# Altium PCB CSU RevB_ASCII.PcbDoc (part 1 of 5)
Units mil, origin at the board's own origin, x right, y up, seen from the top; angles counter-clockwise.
Board outline 5905.51 x 4330.71 mil, 8 copper layers (Top Layer, InternalPlane1, MidLayer1, InternalPlane2, MidLayer2, InternalPlane3, MidLayer3, Bottom Layer); 265 components, 387 nets, 1910 pads, 1151 vias.
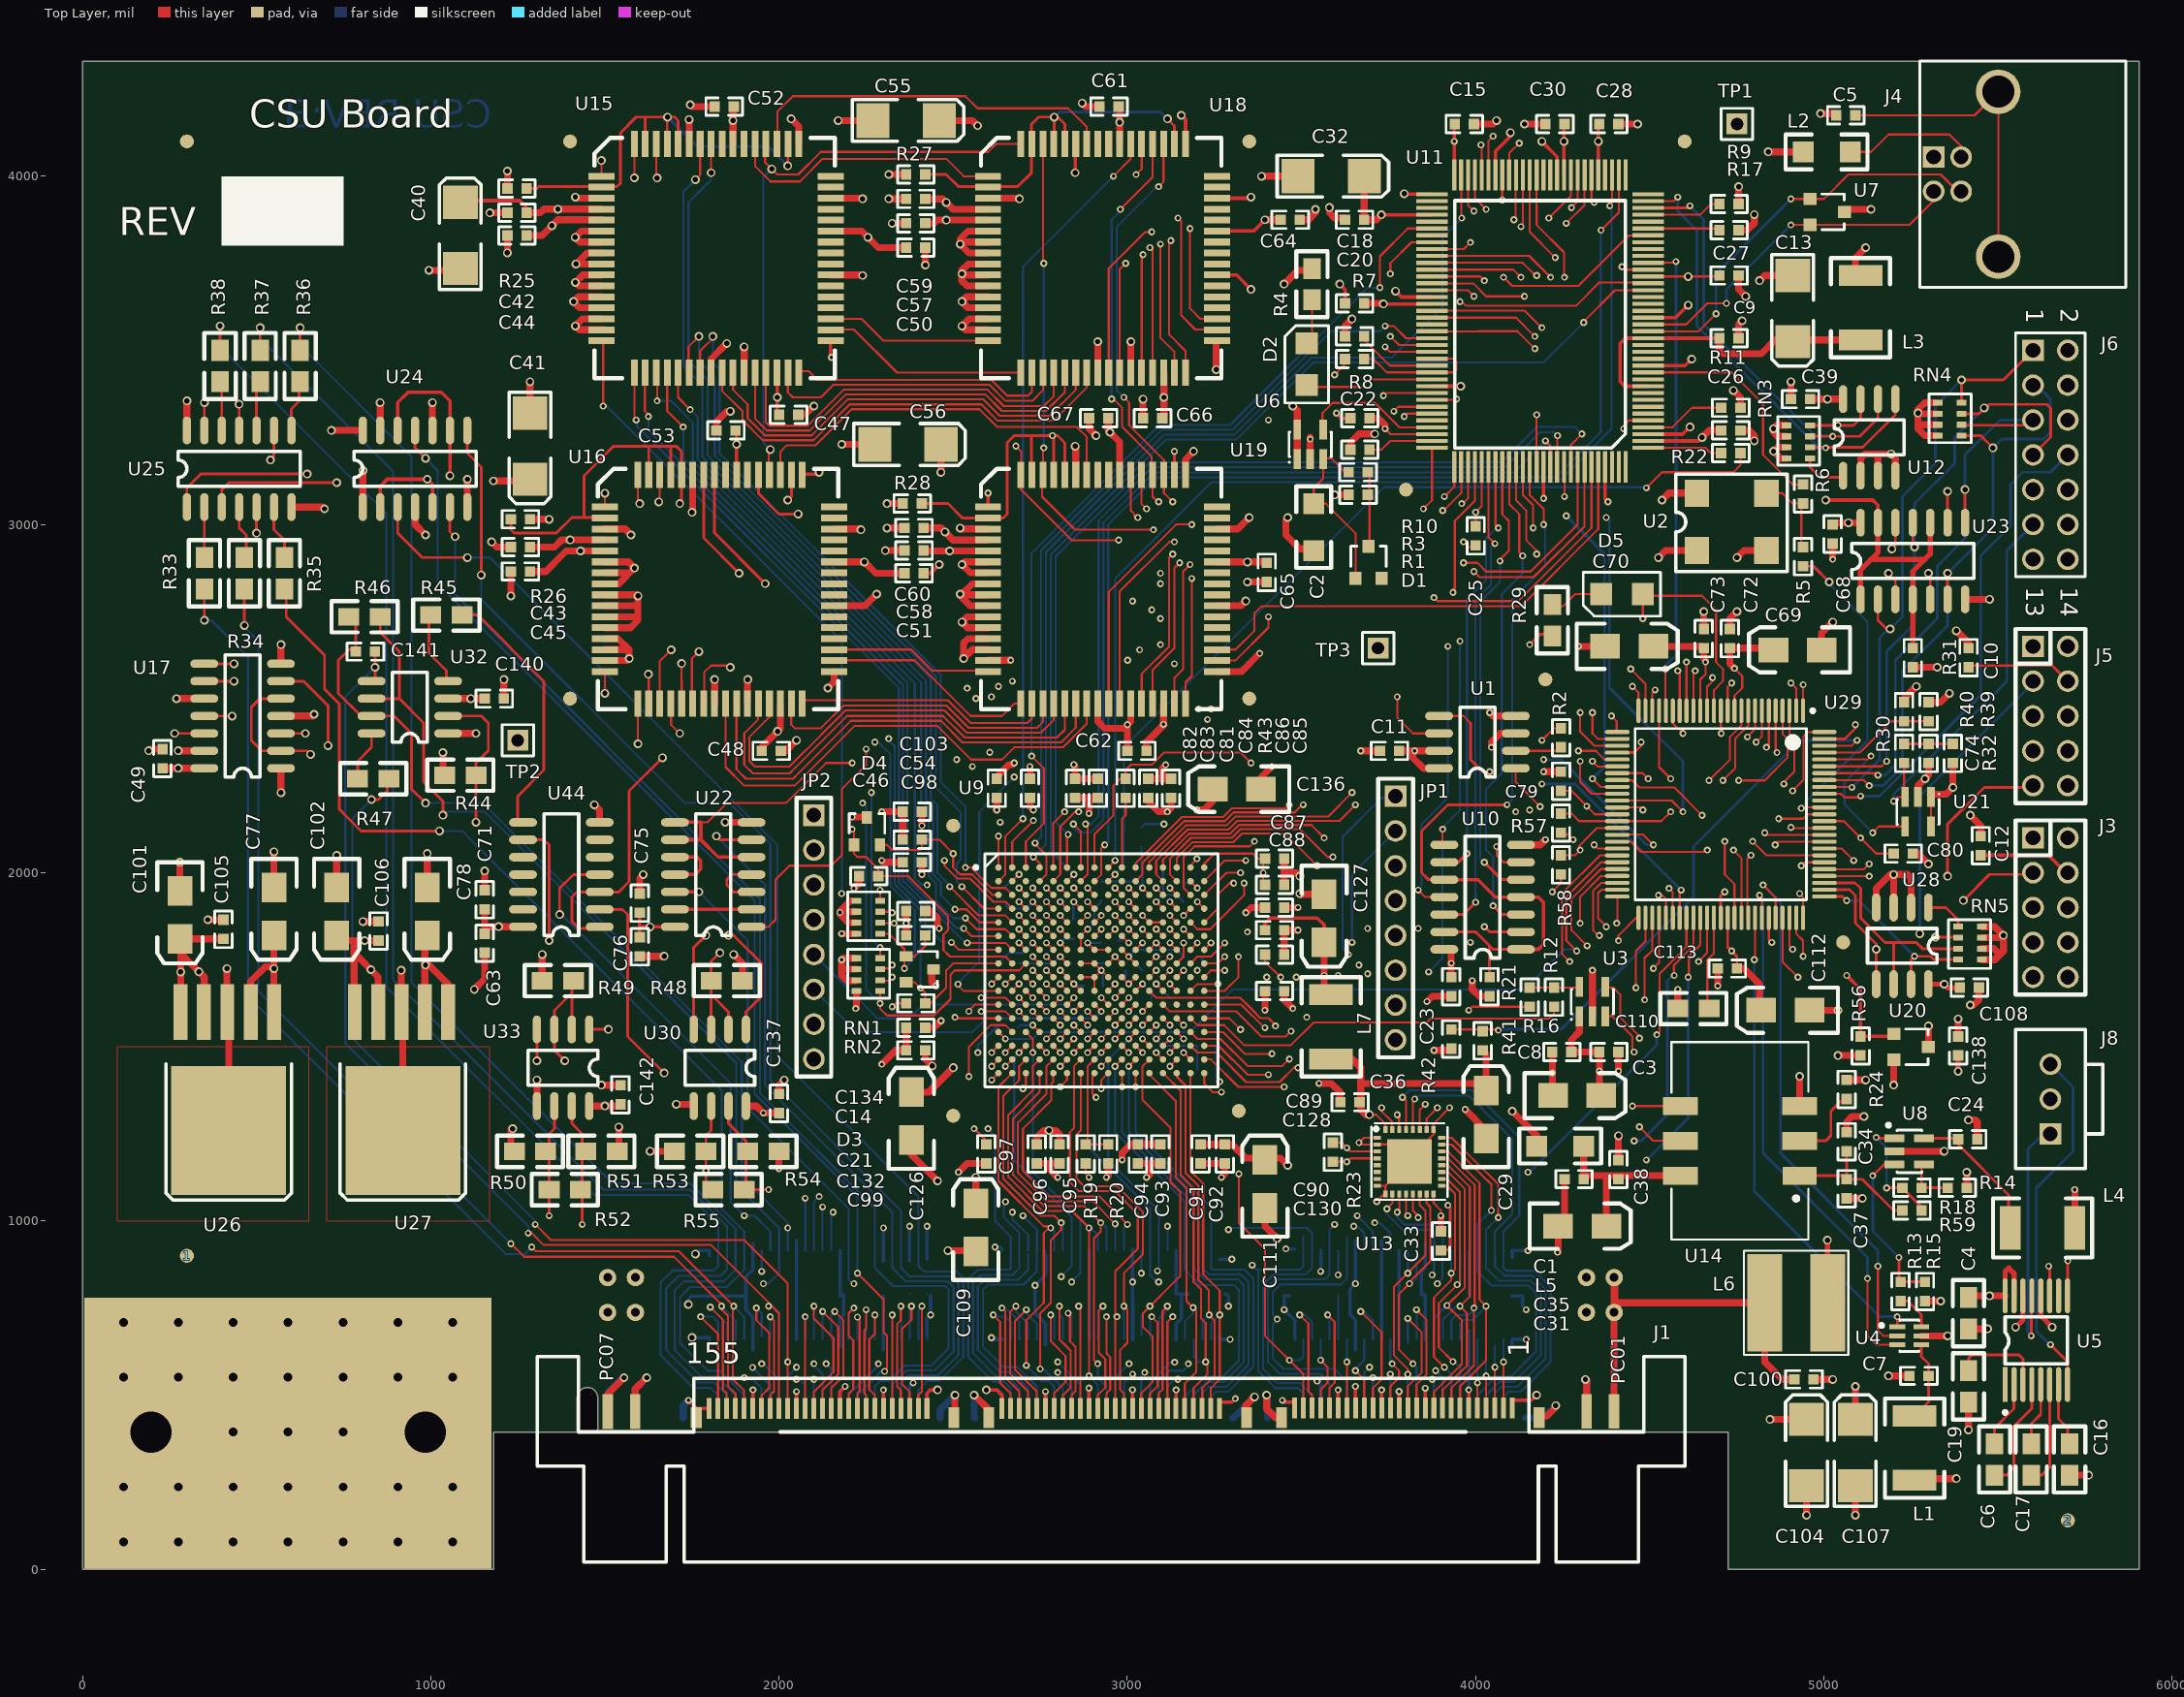
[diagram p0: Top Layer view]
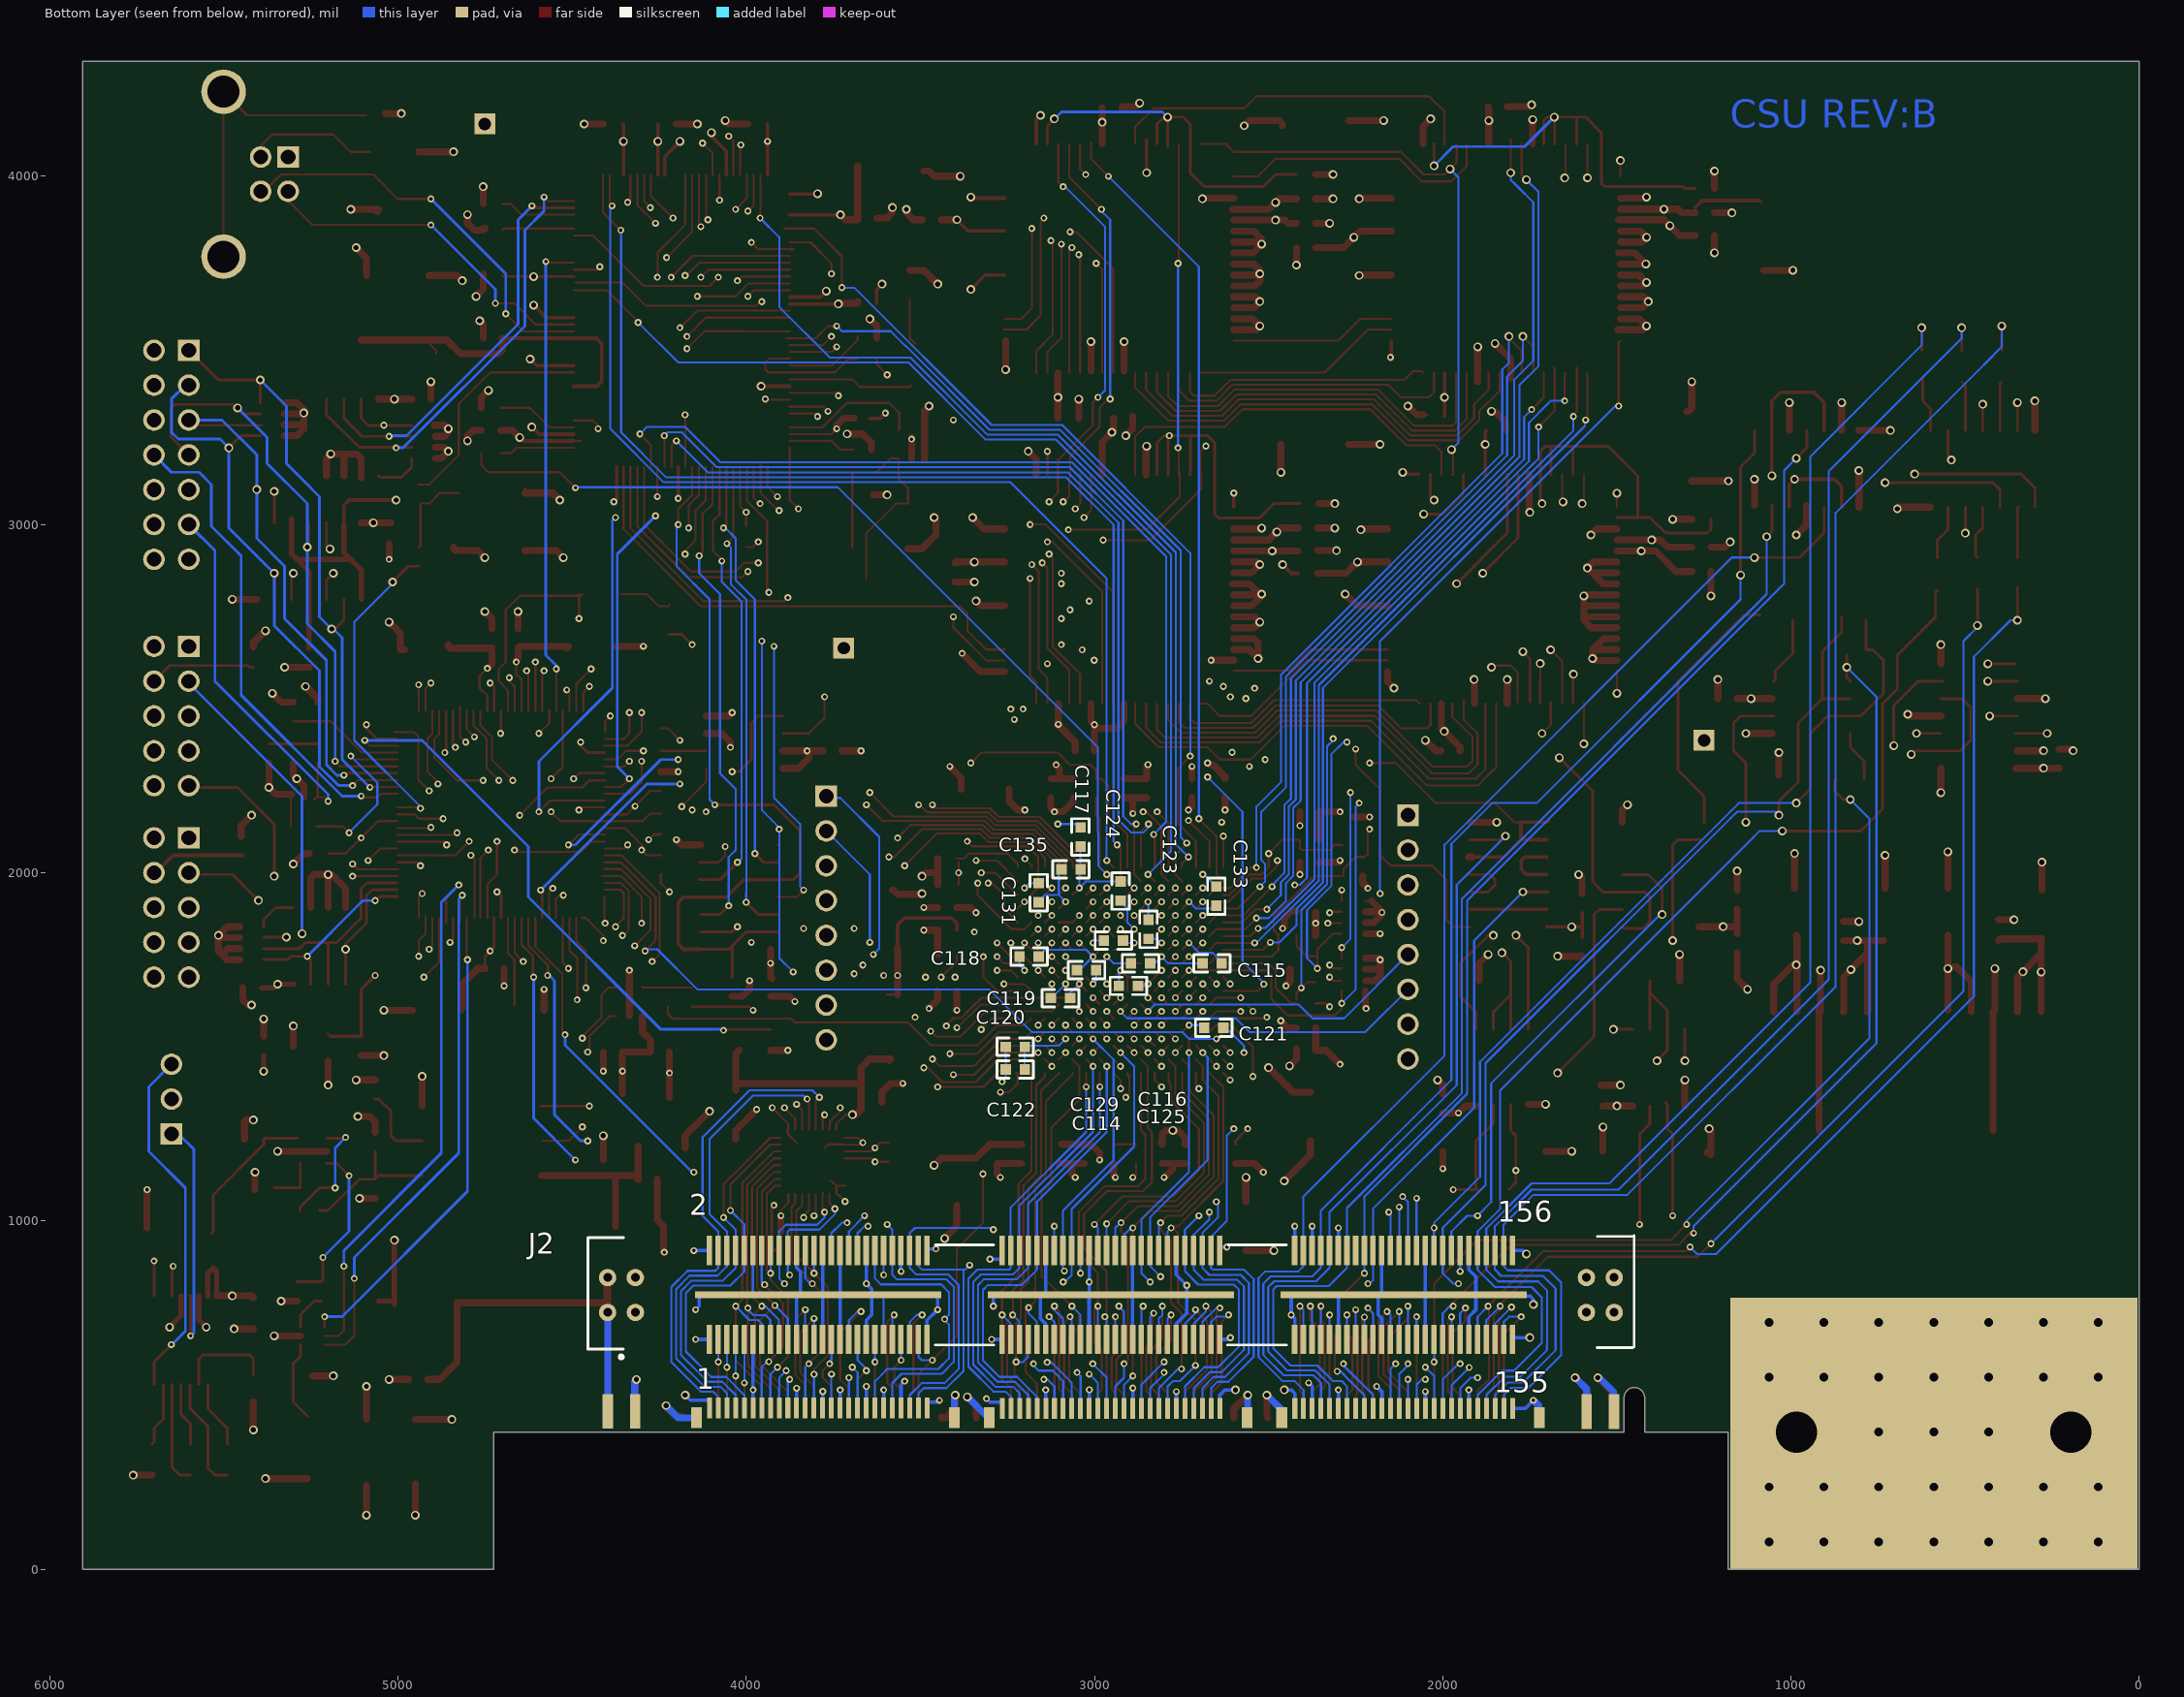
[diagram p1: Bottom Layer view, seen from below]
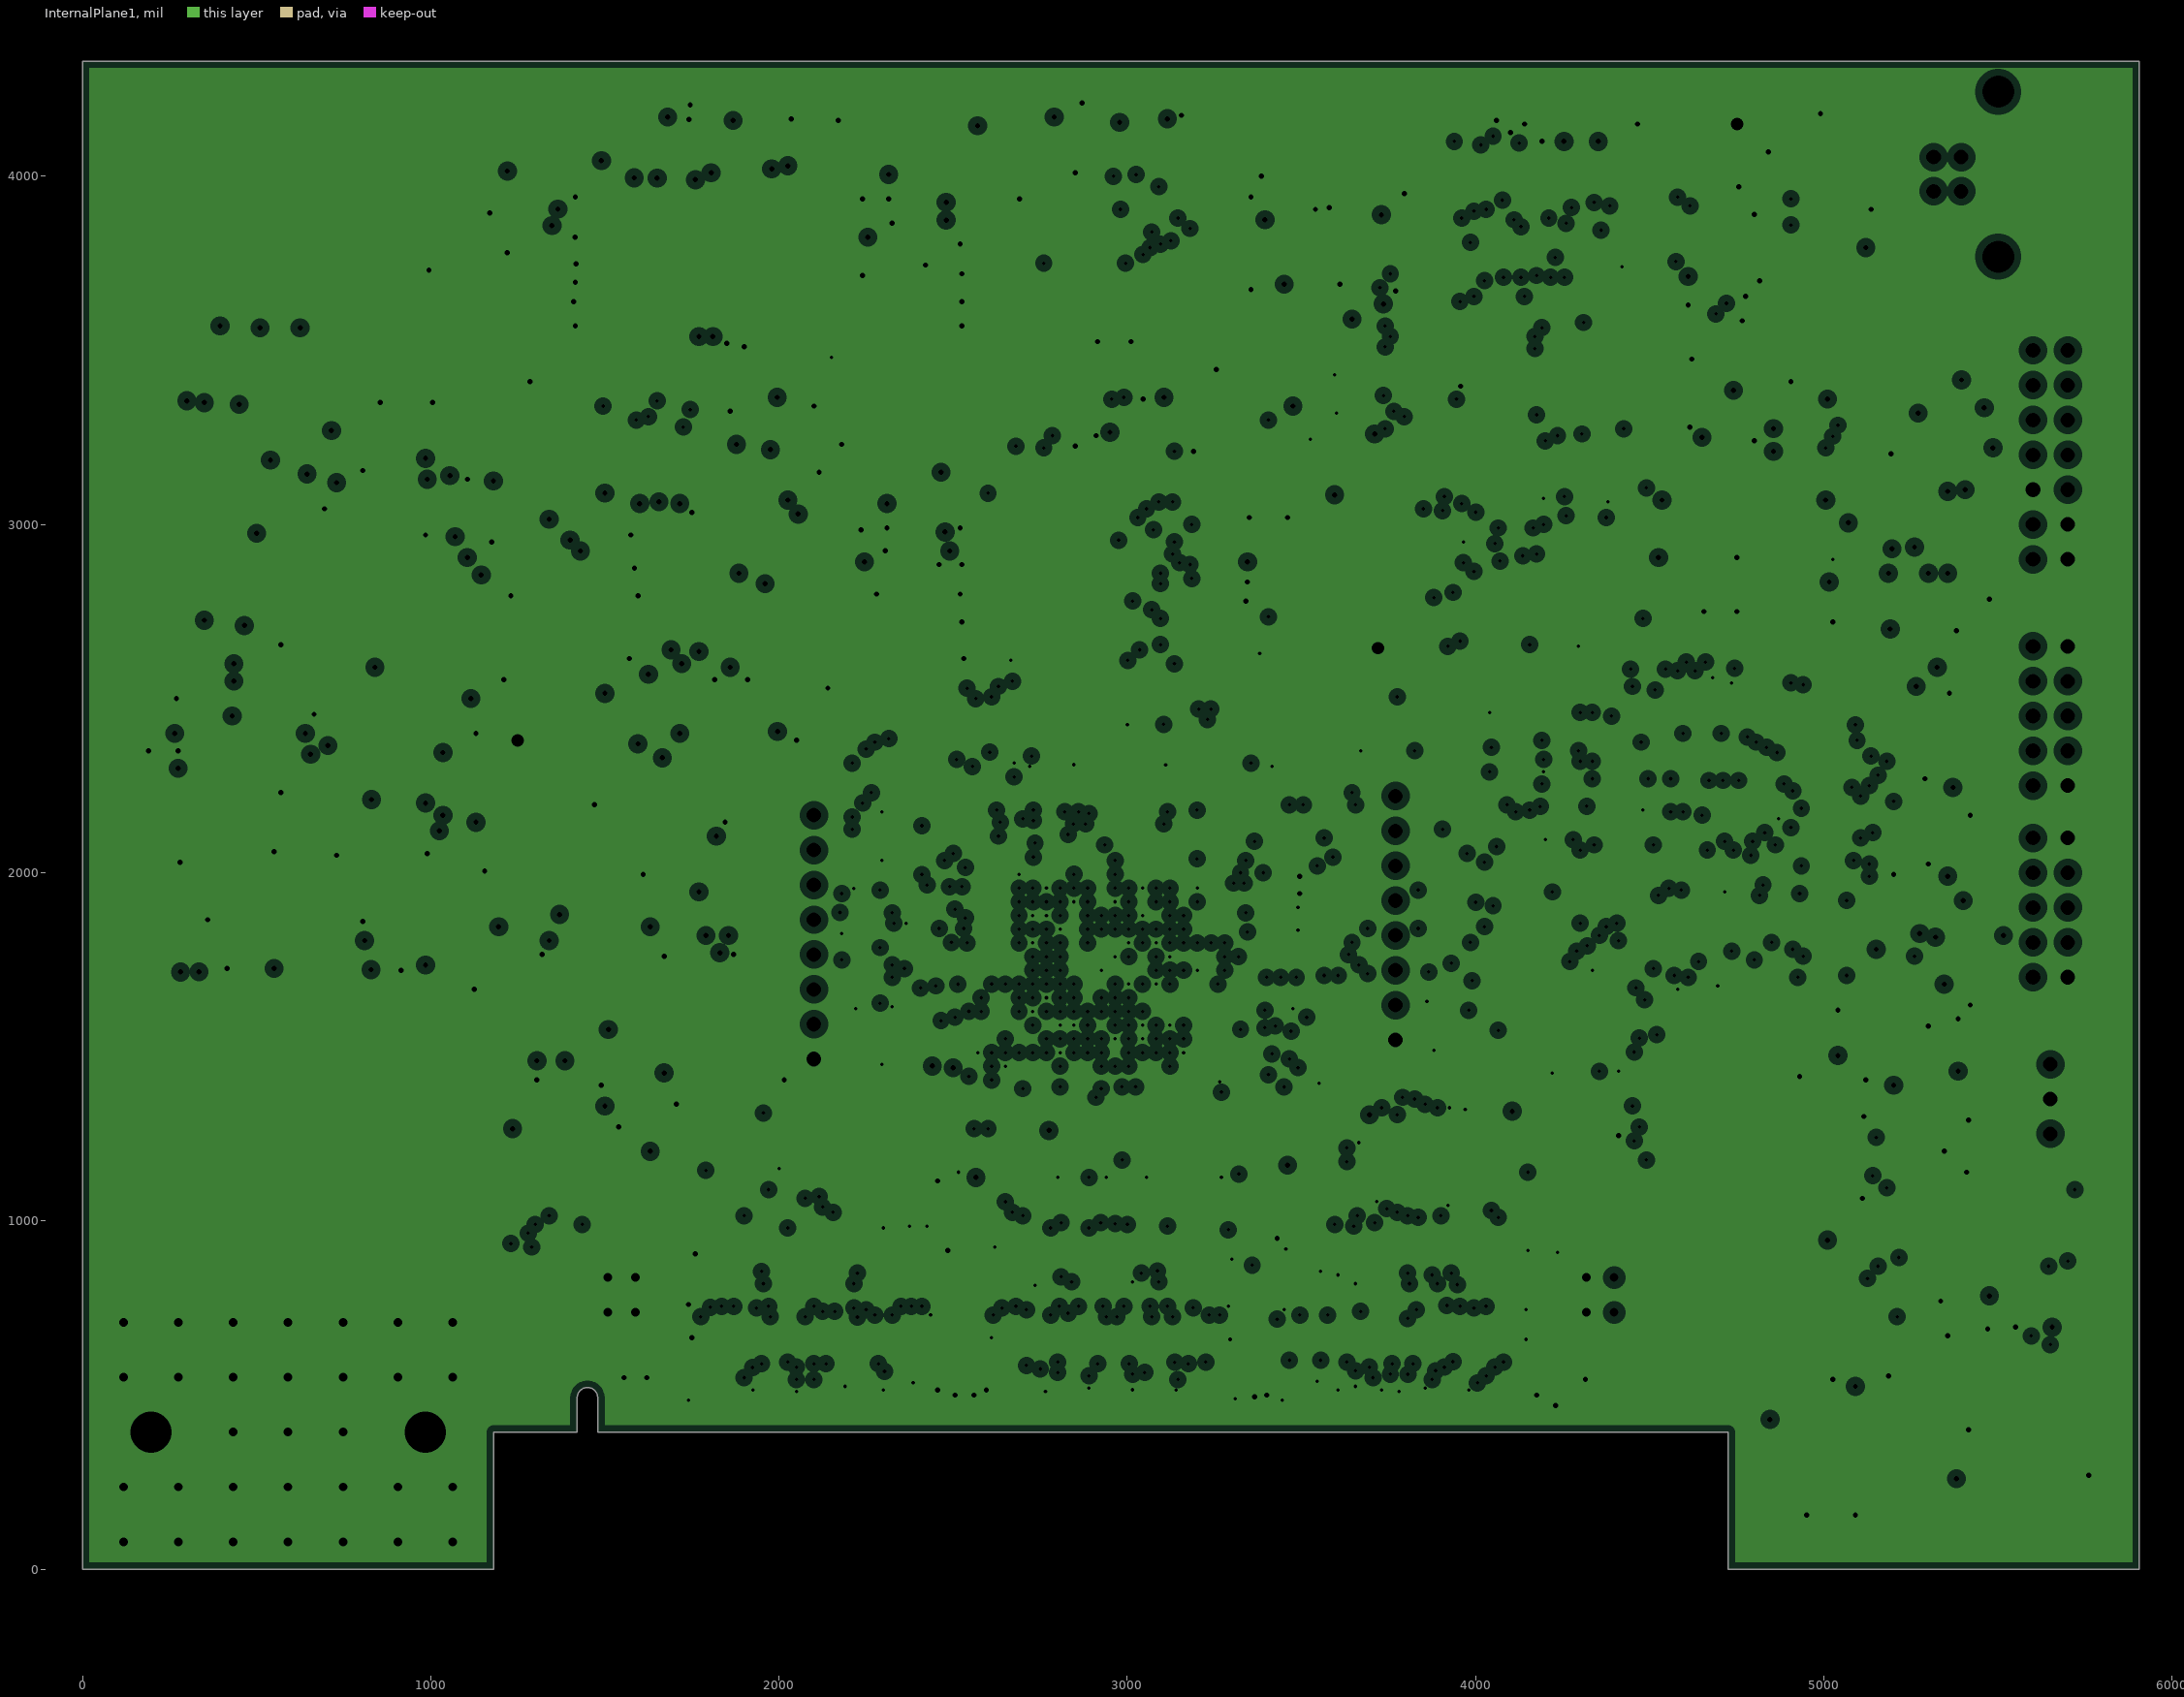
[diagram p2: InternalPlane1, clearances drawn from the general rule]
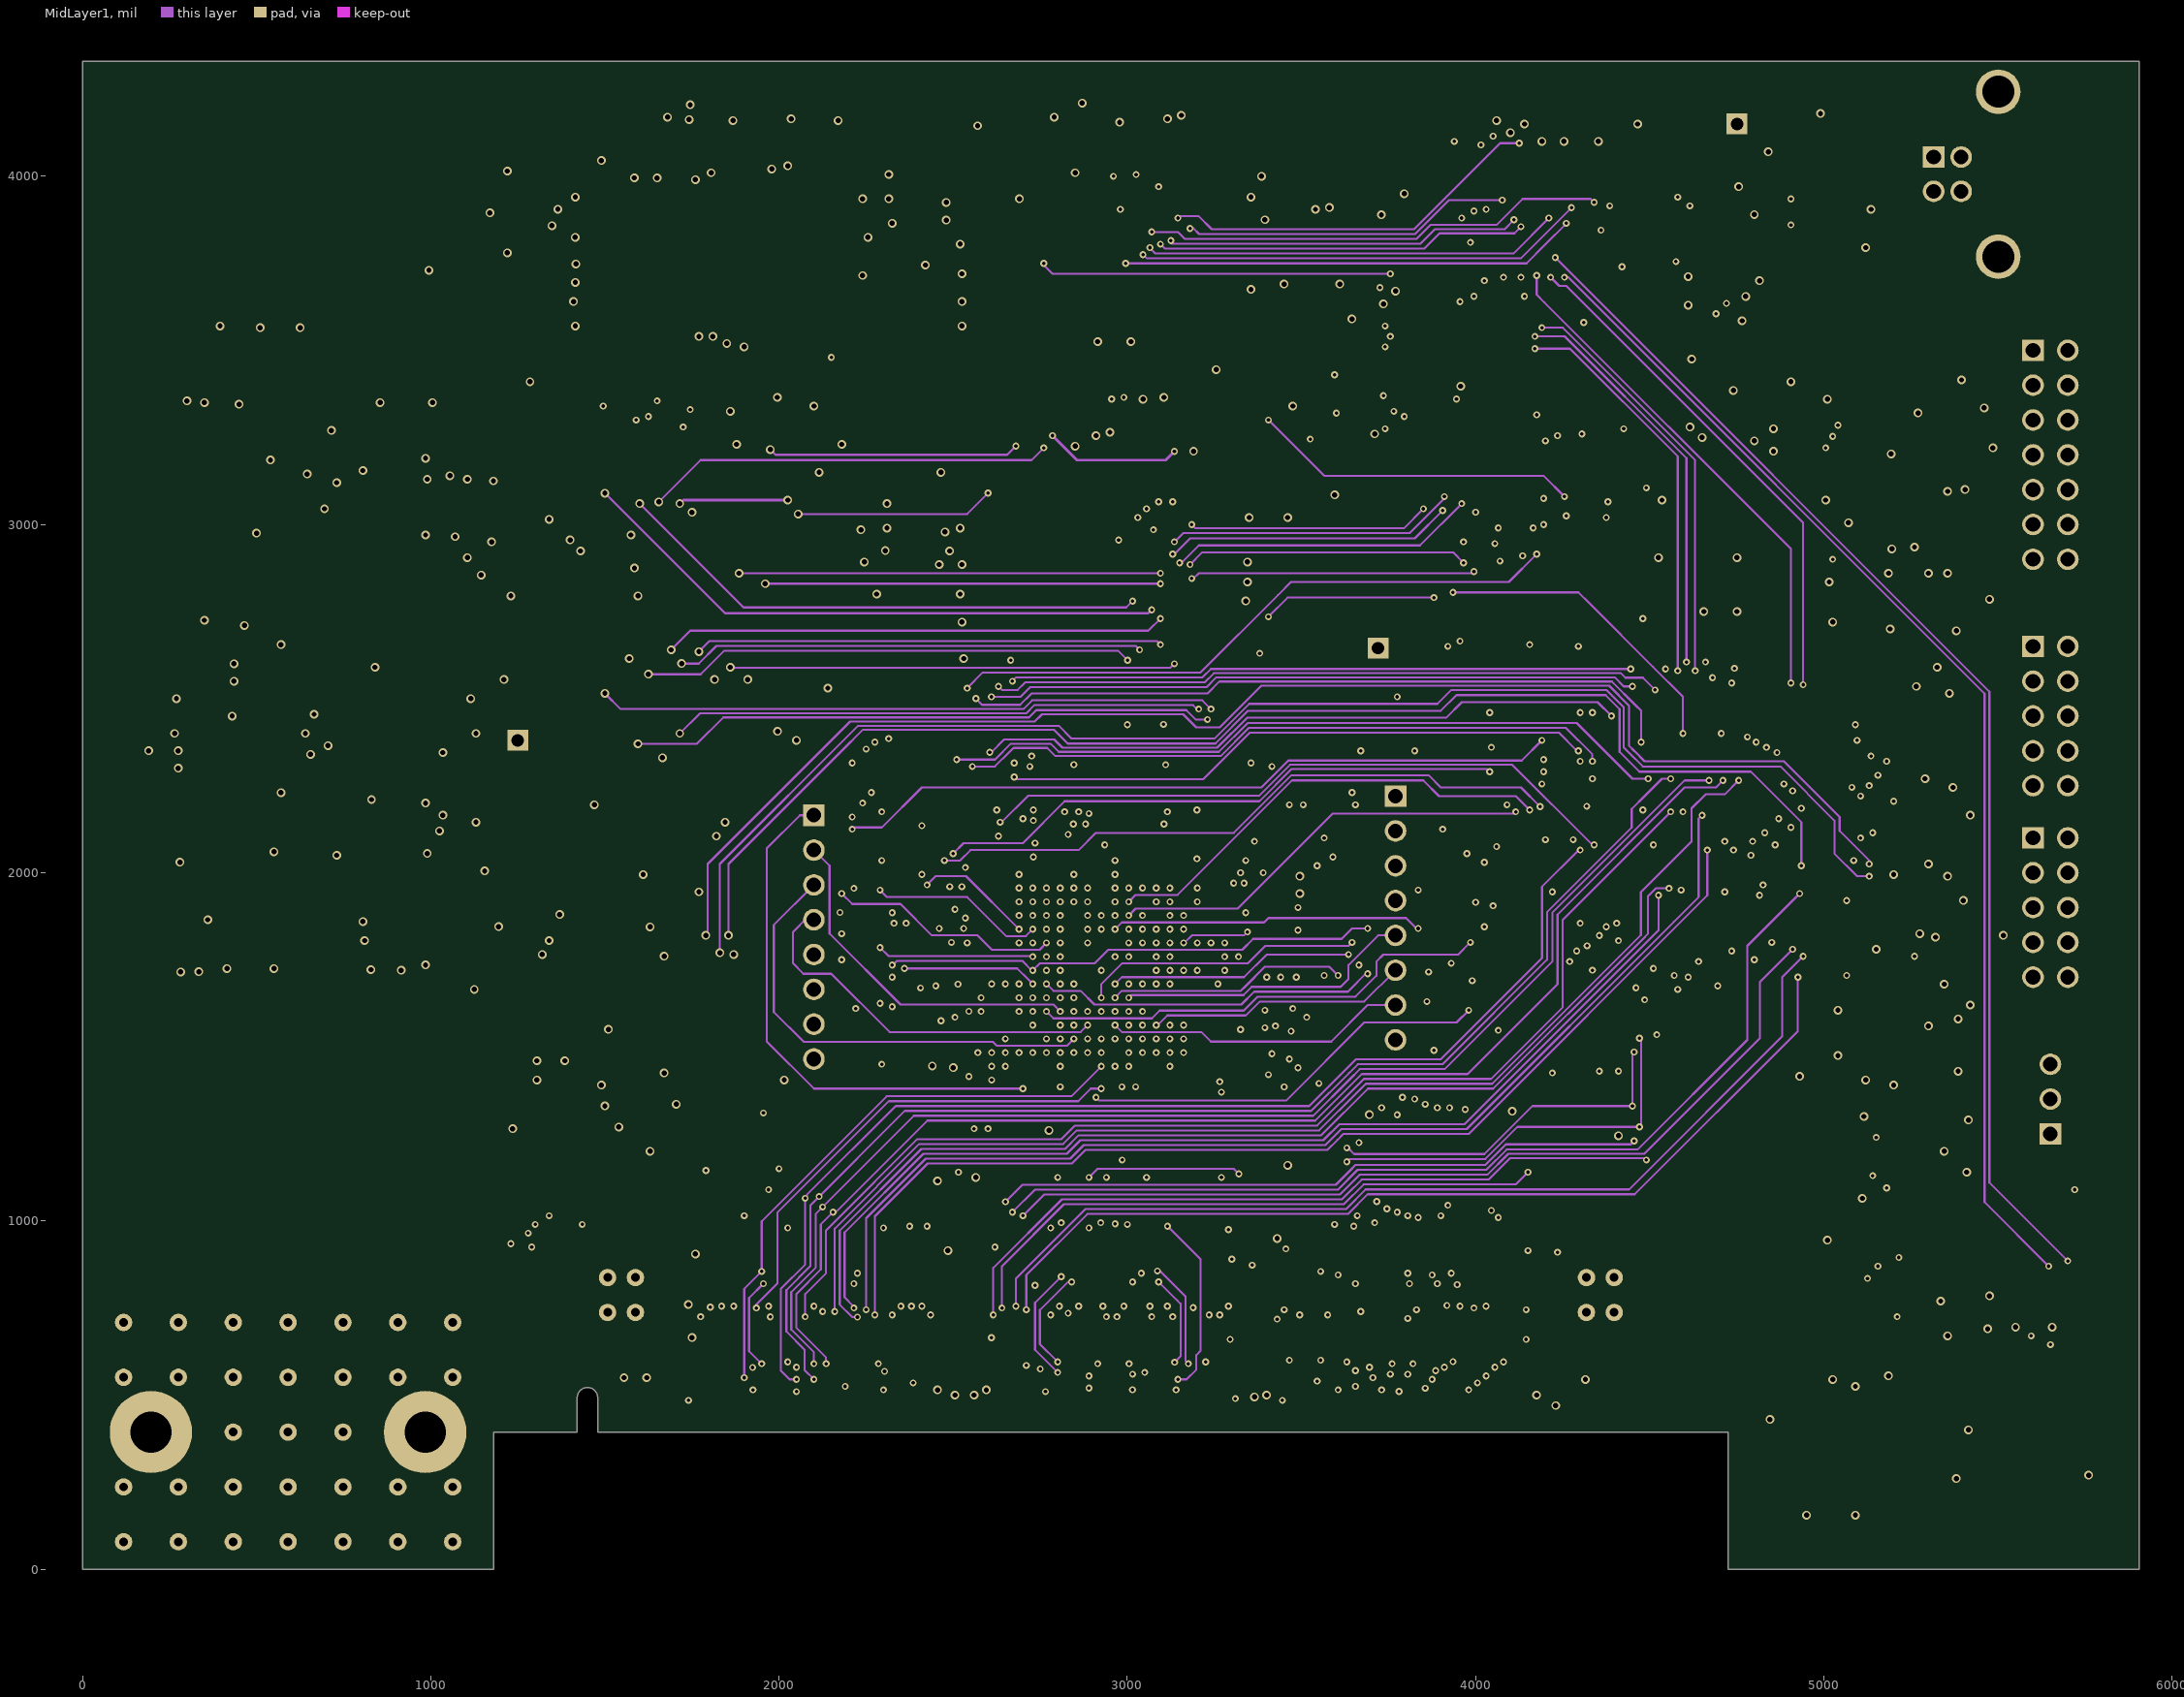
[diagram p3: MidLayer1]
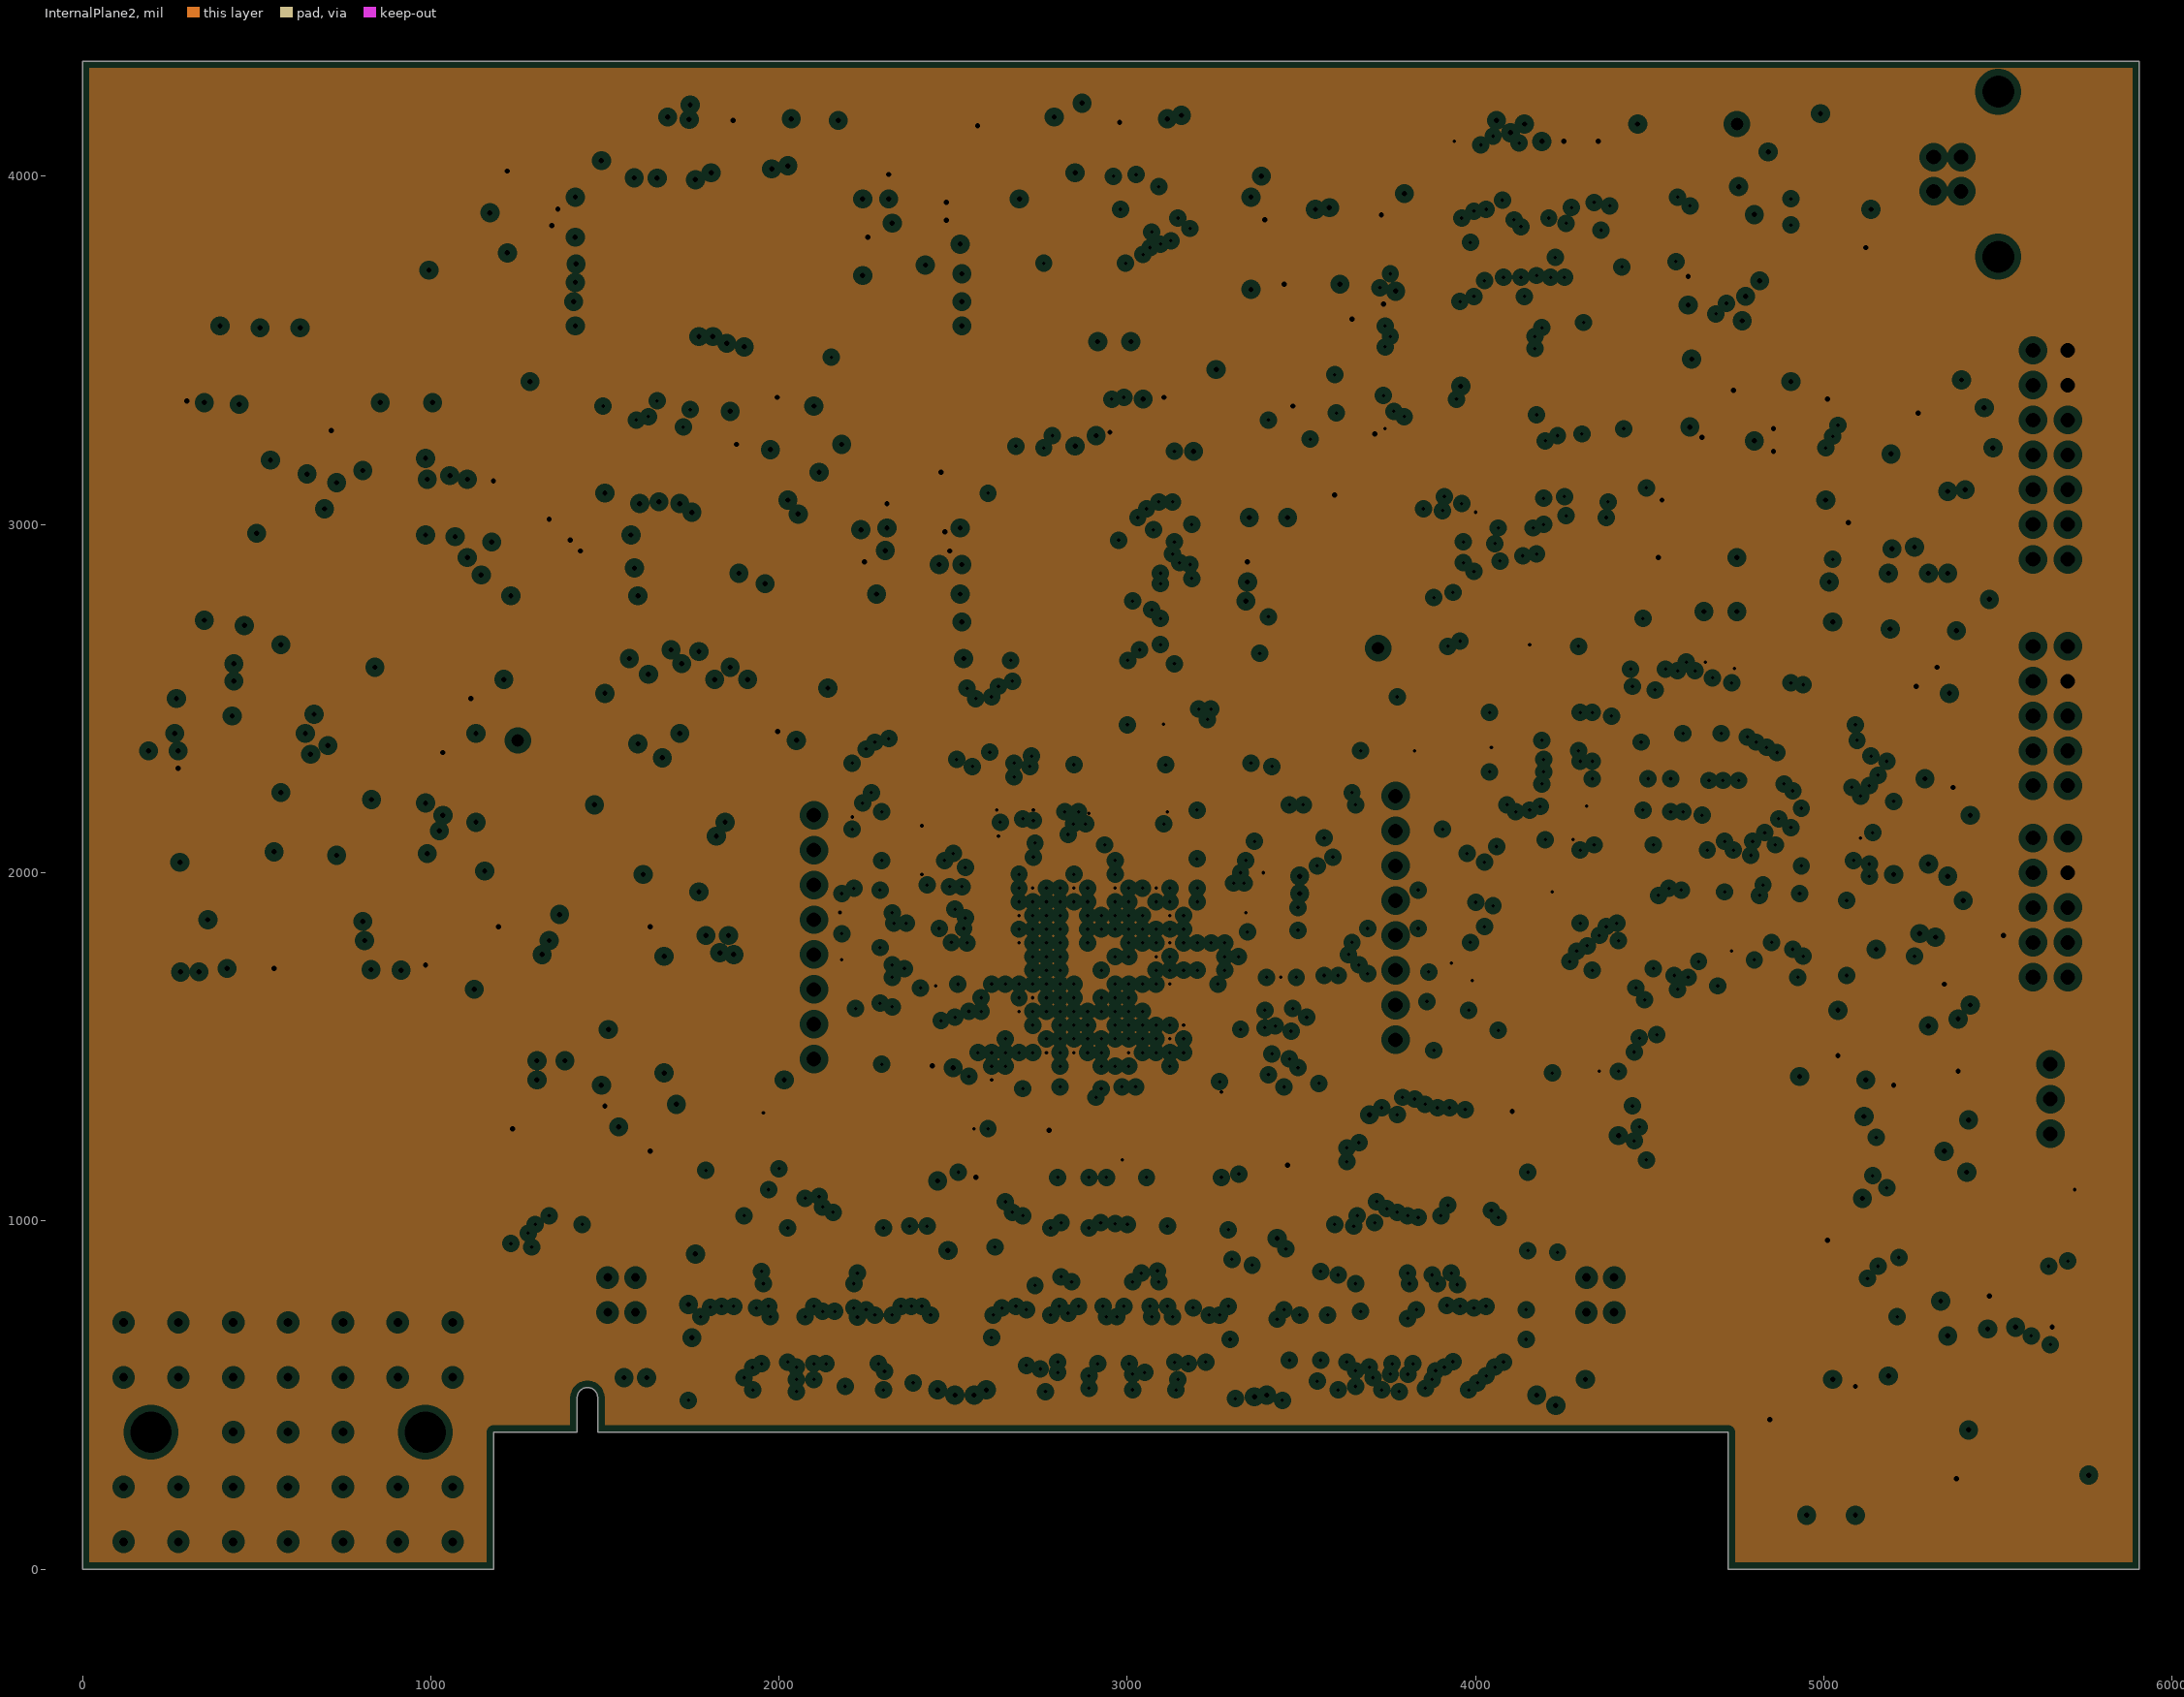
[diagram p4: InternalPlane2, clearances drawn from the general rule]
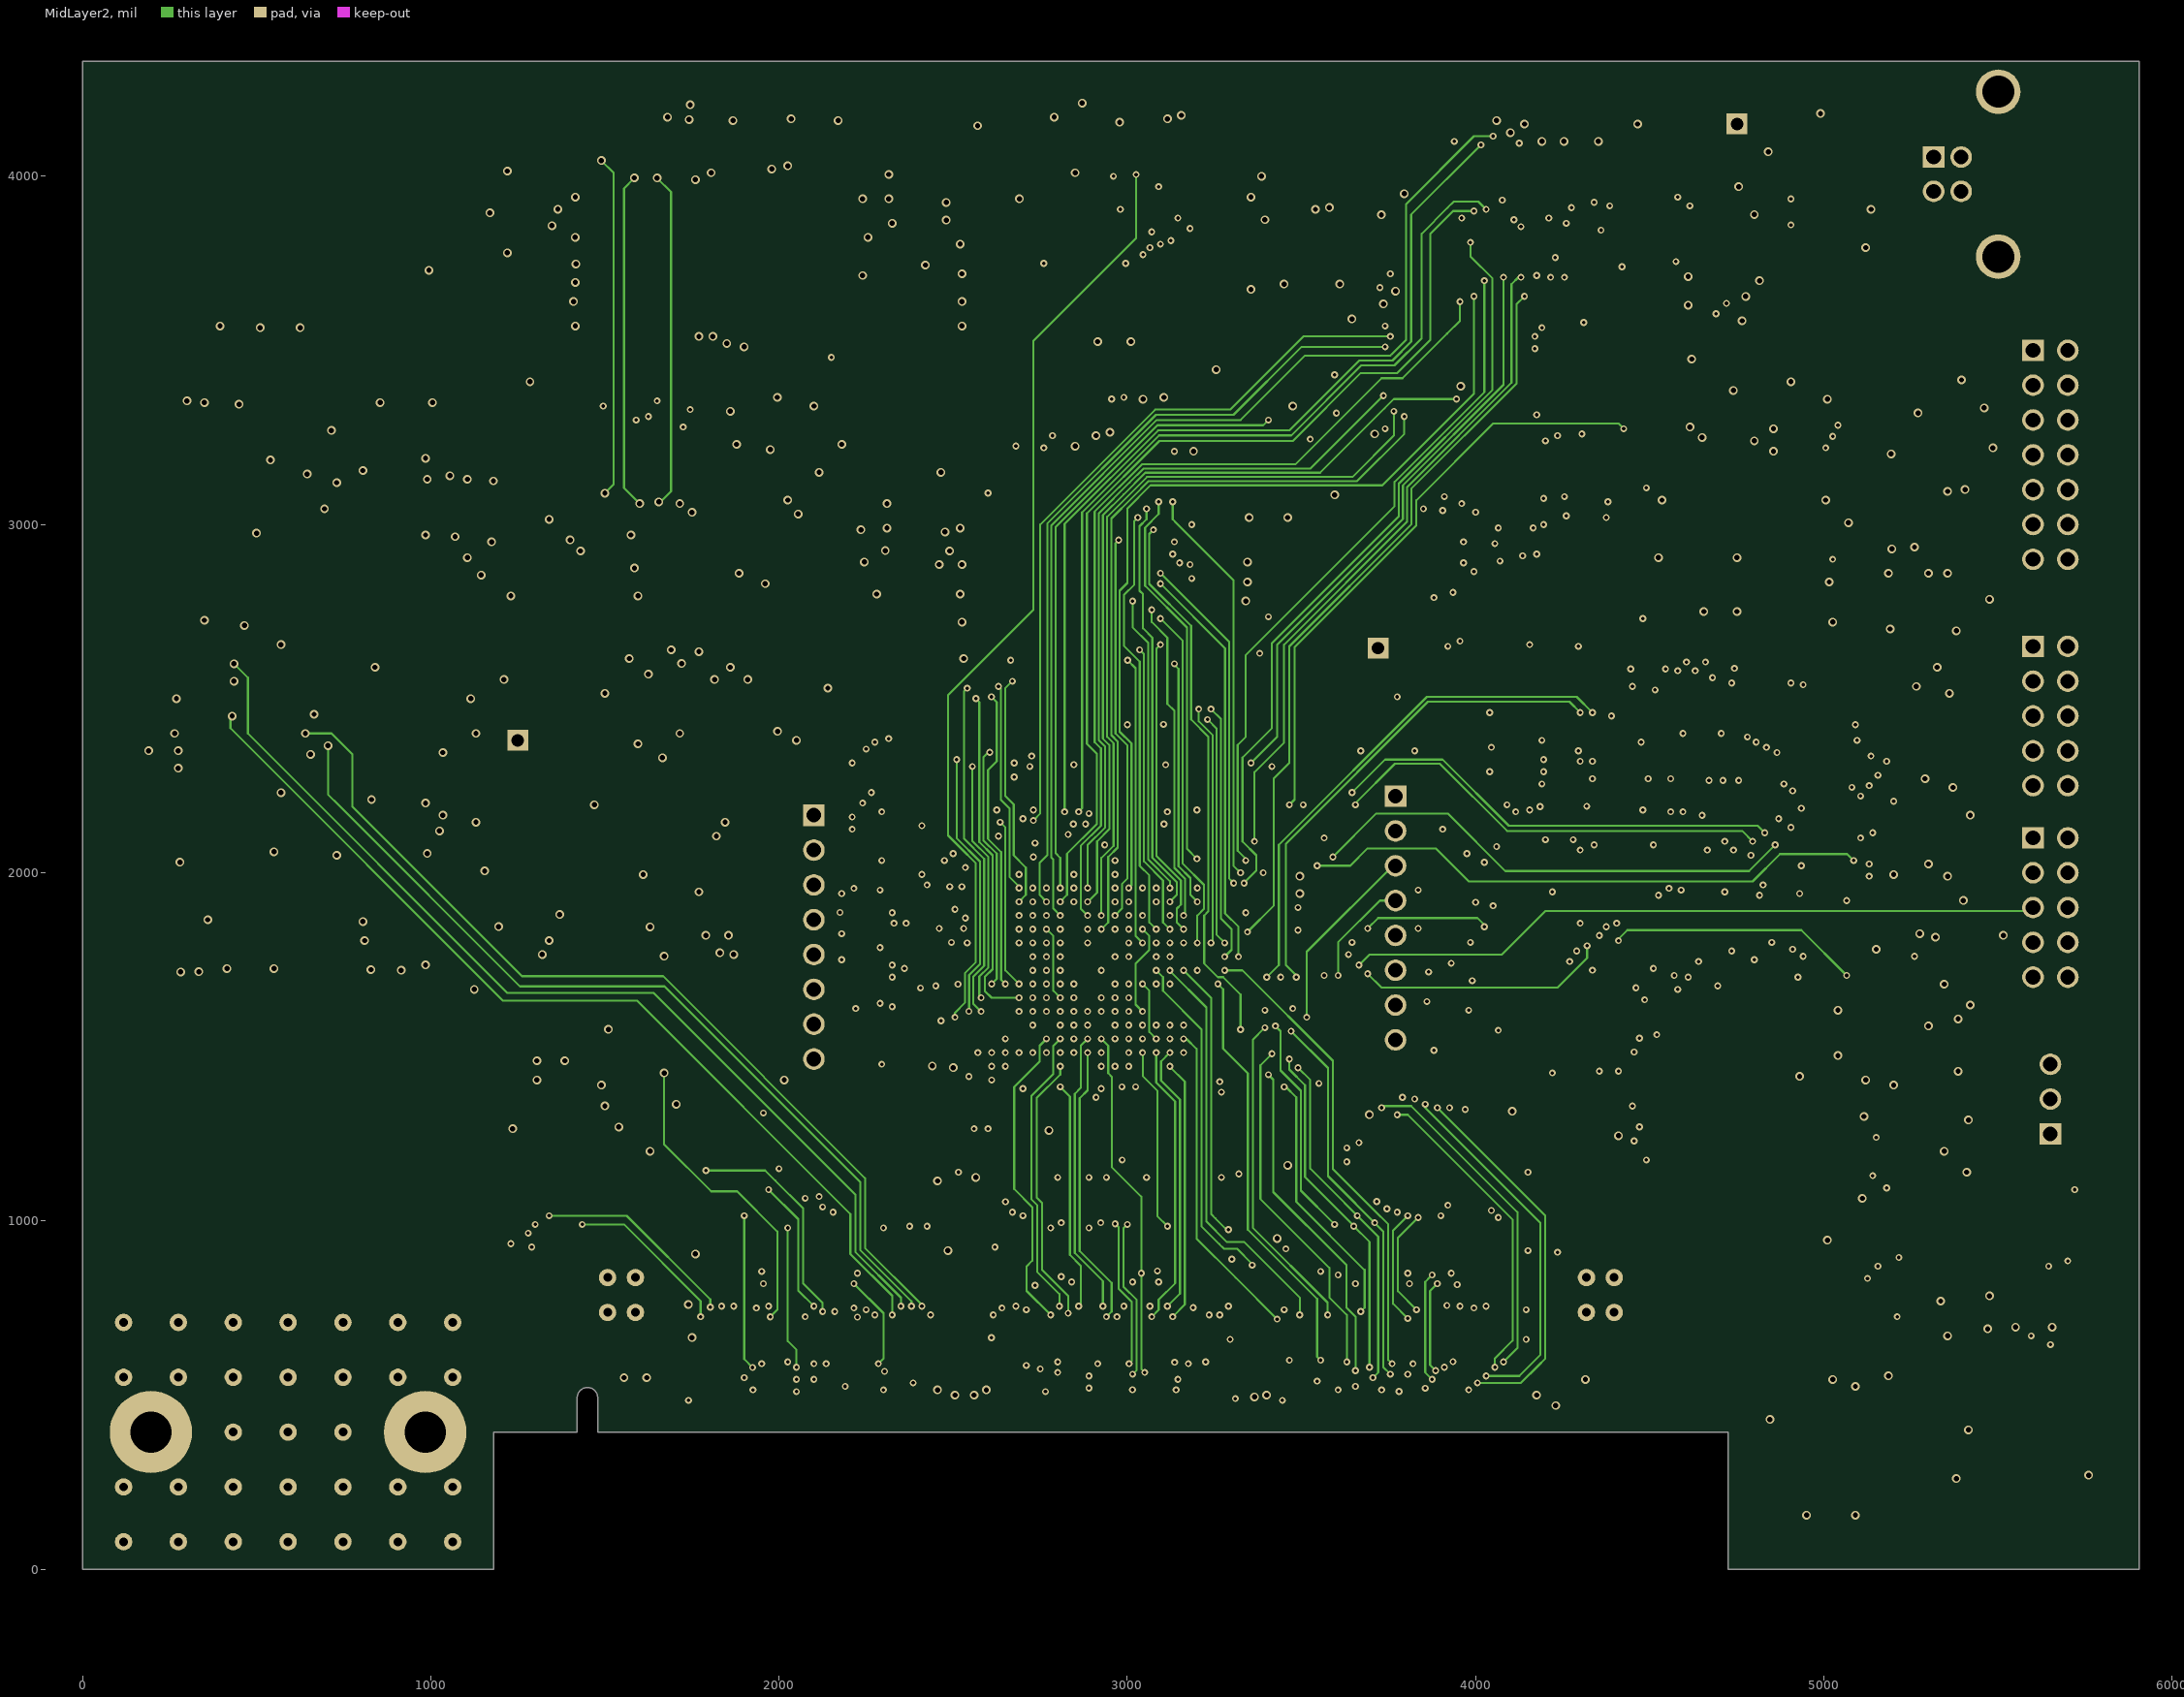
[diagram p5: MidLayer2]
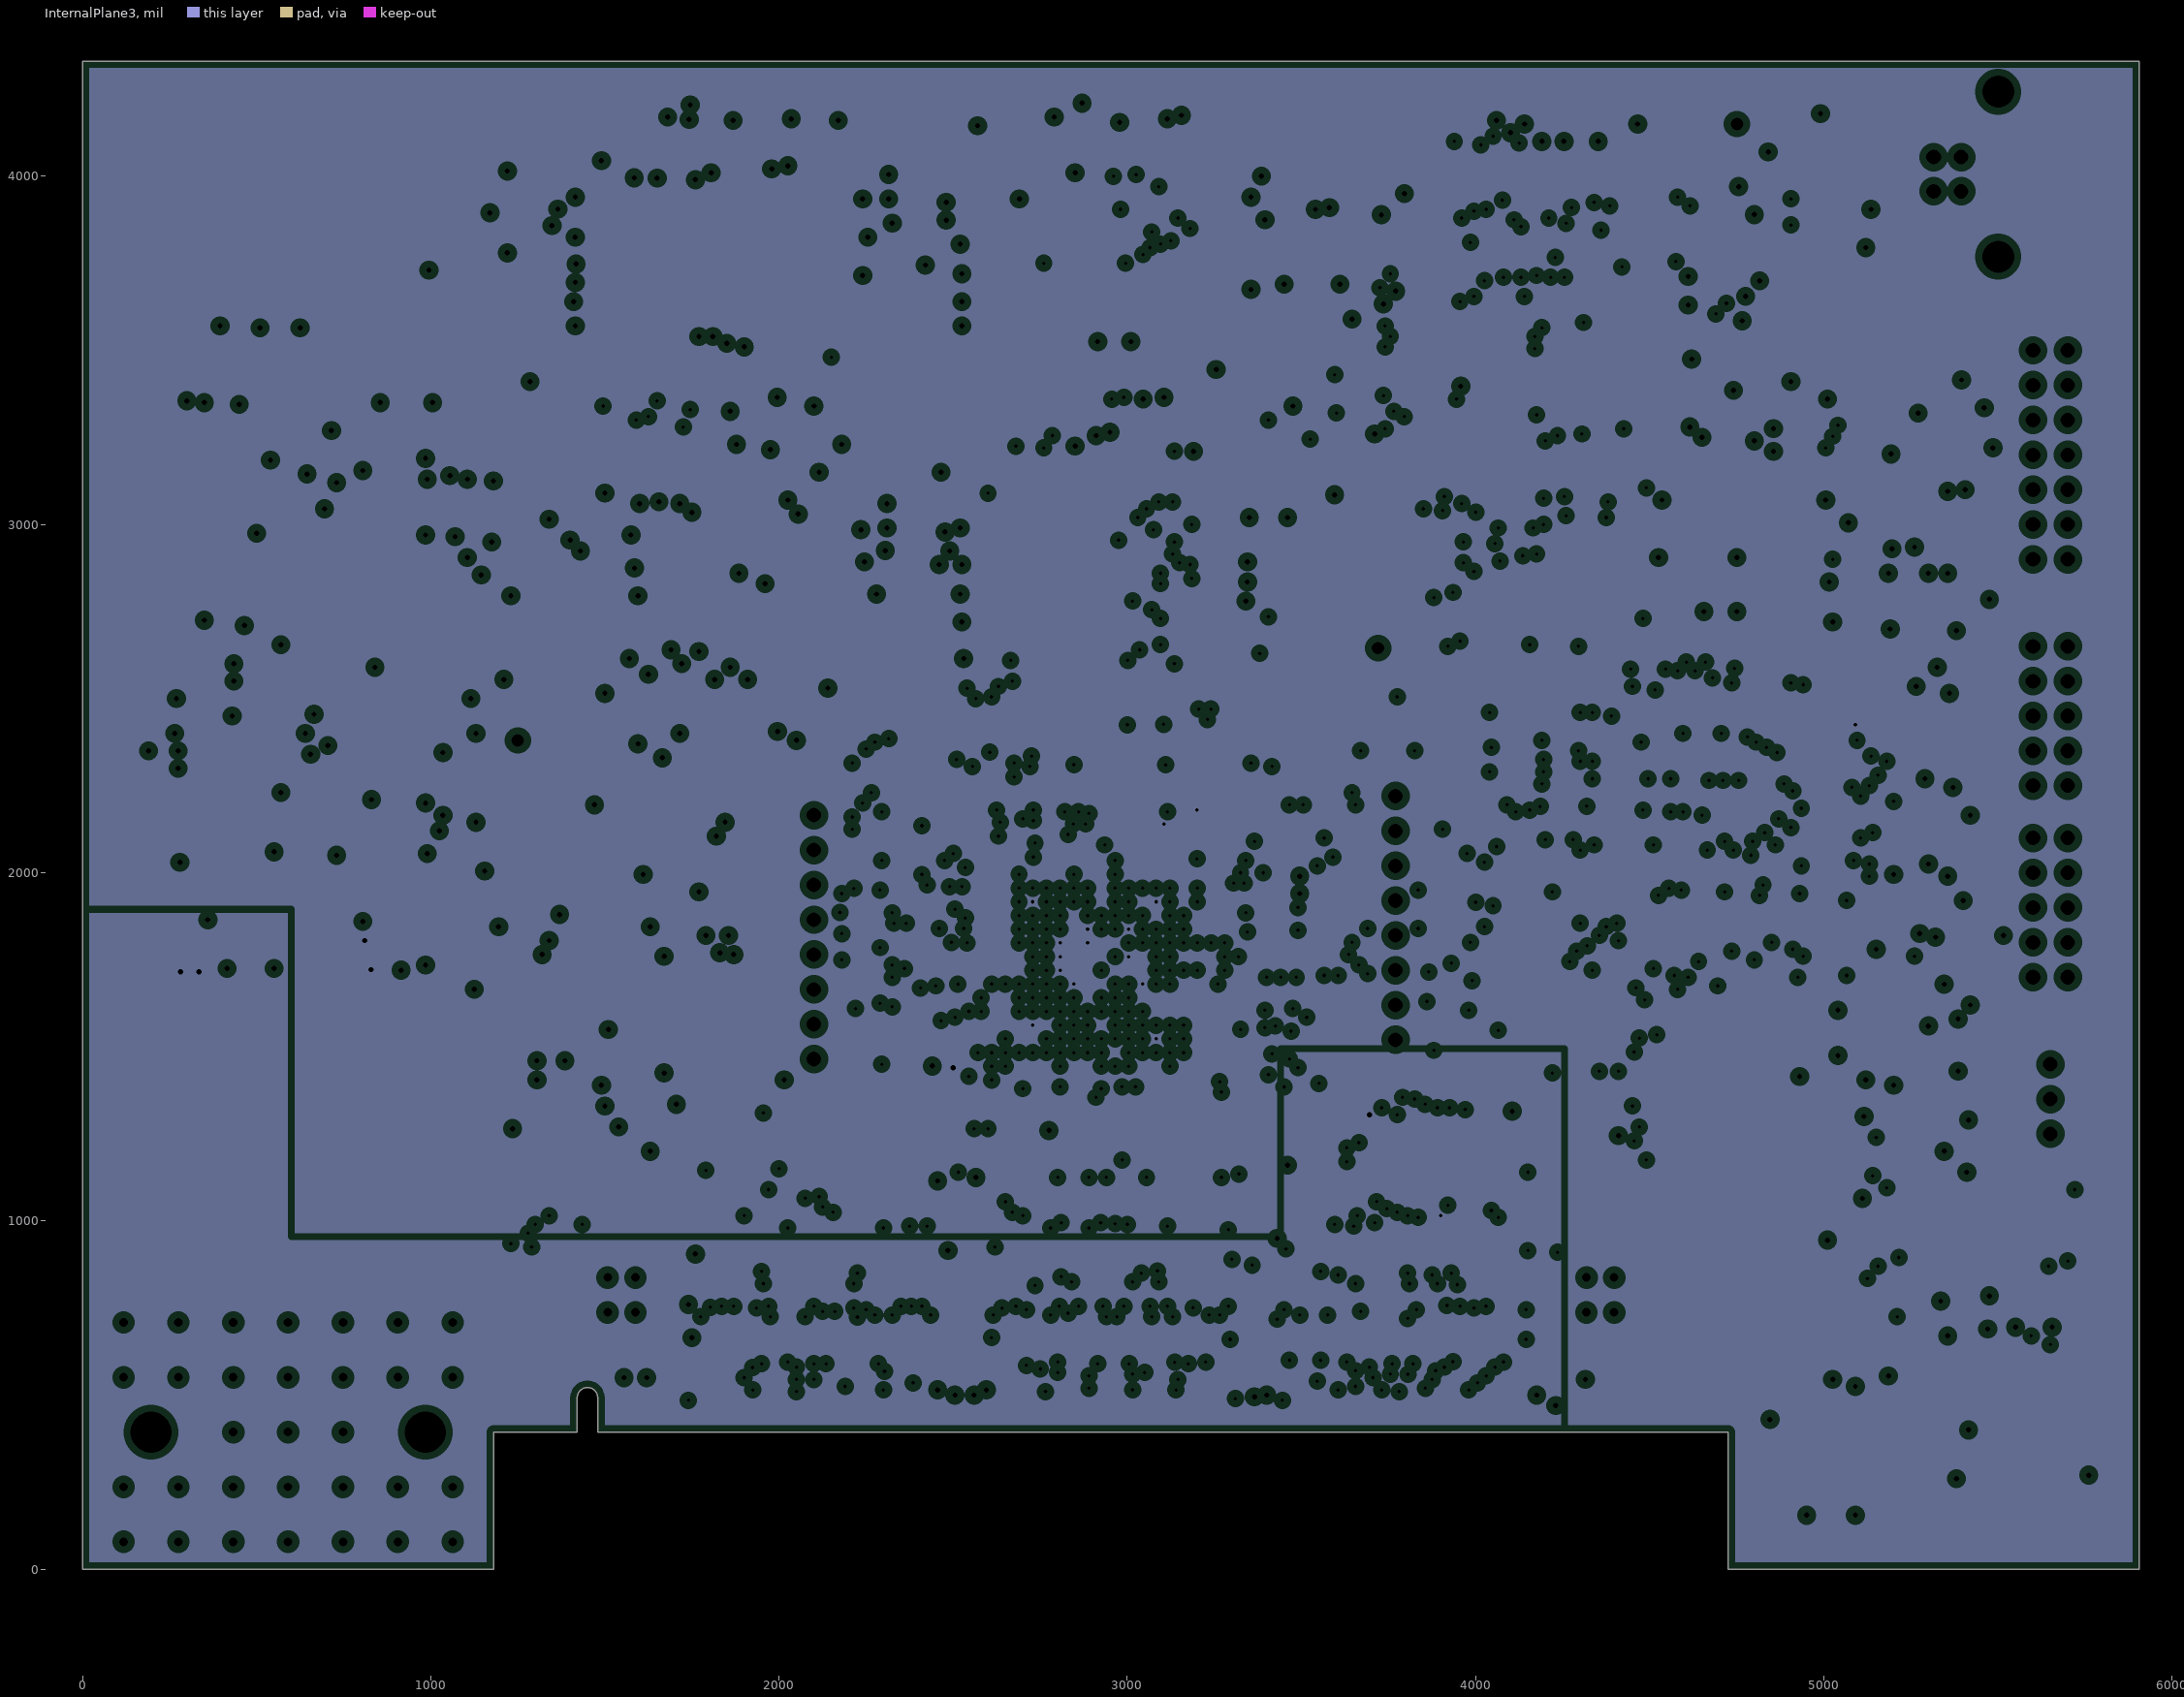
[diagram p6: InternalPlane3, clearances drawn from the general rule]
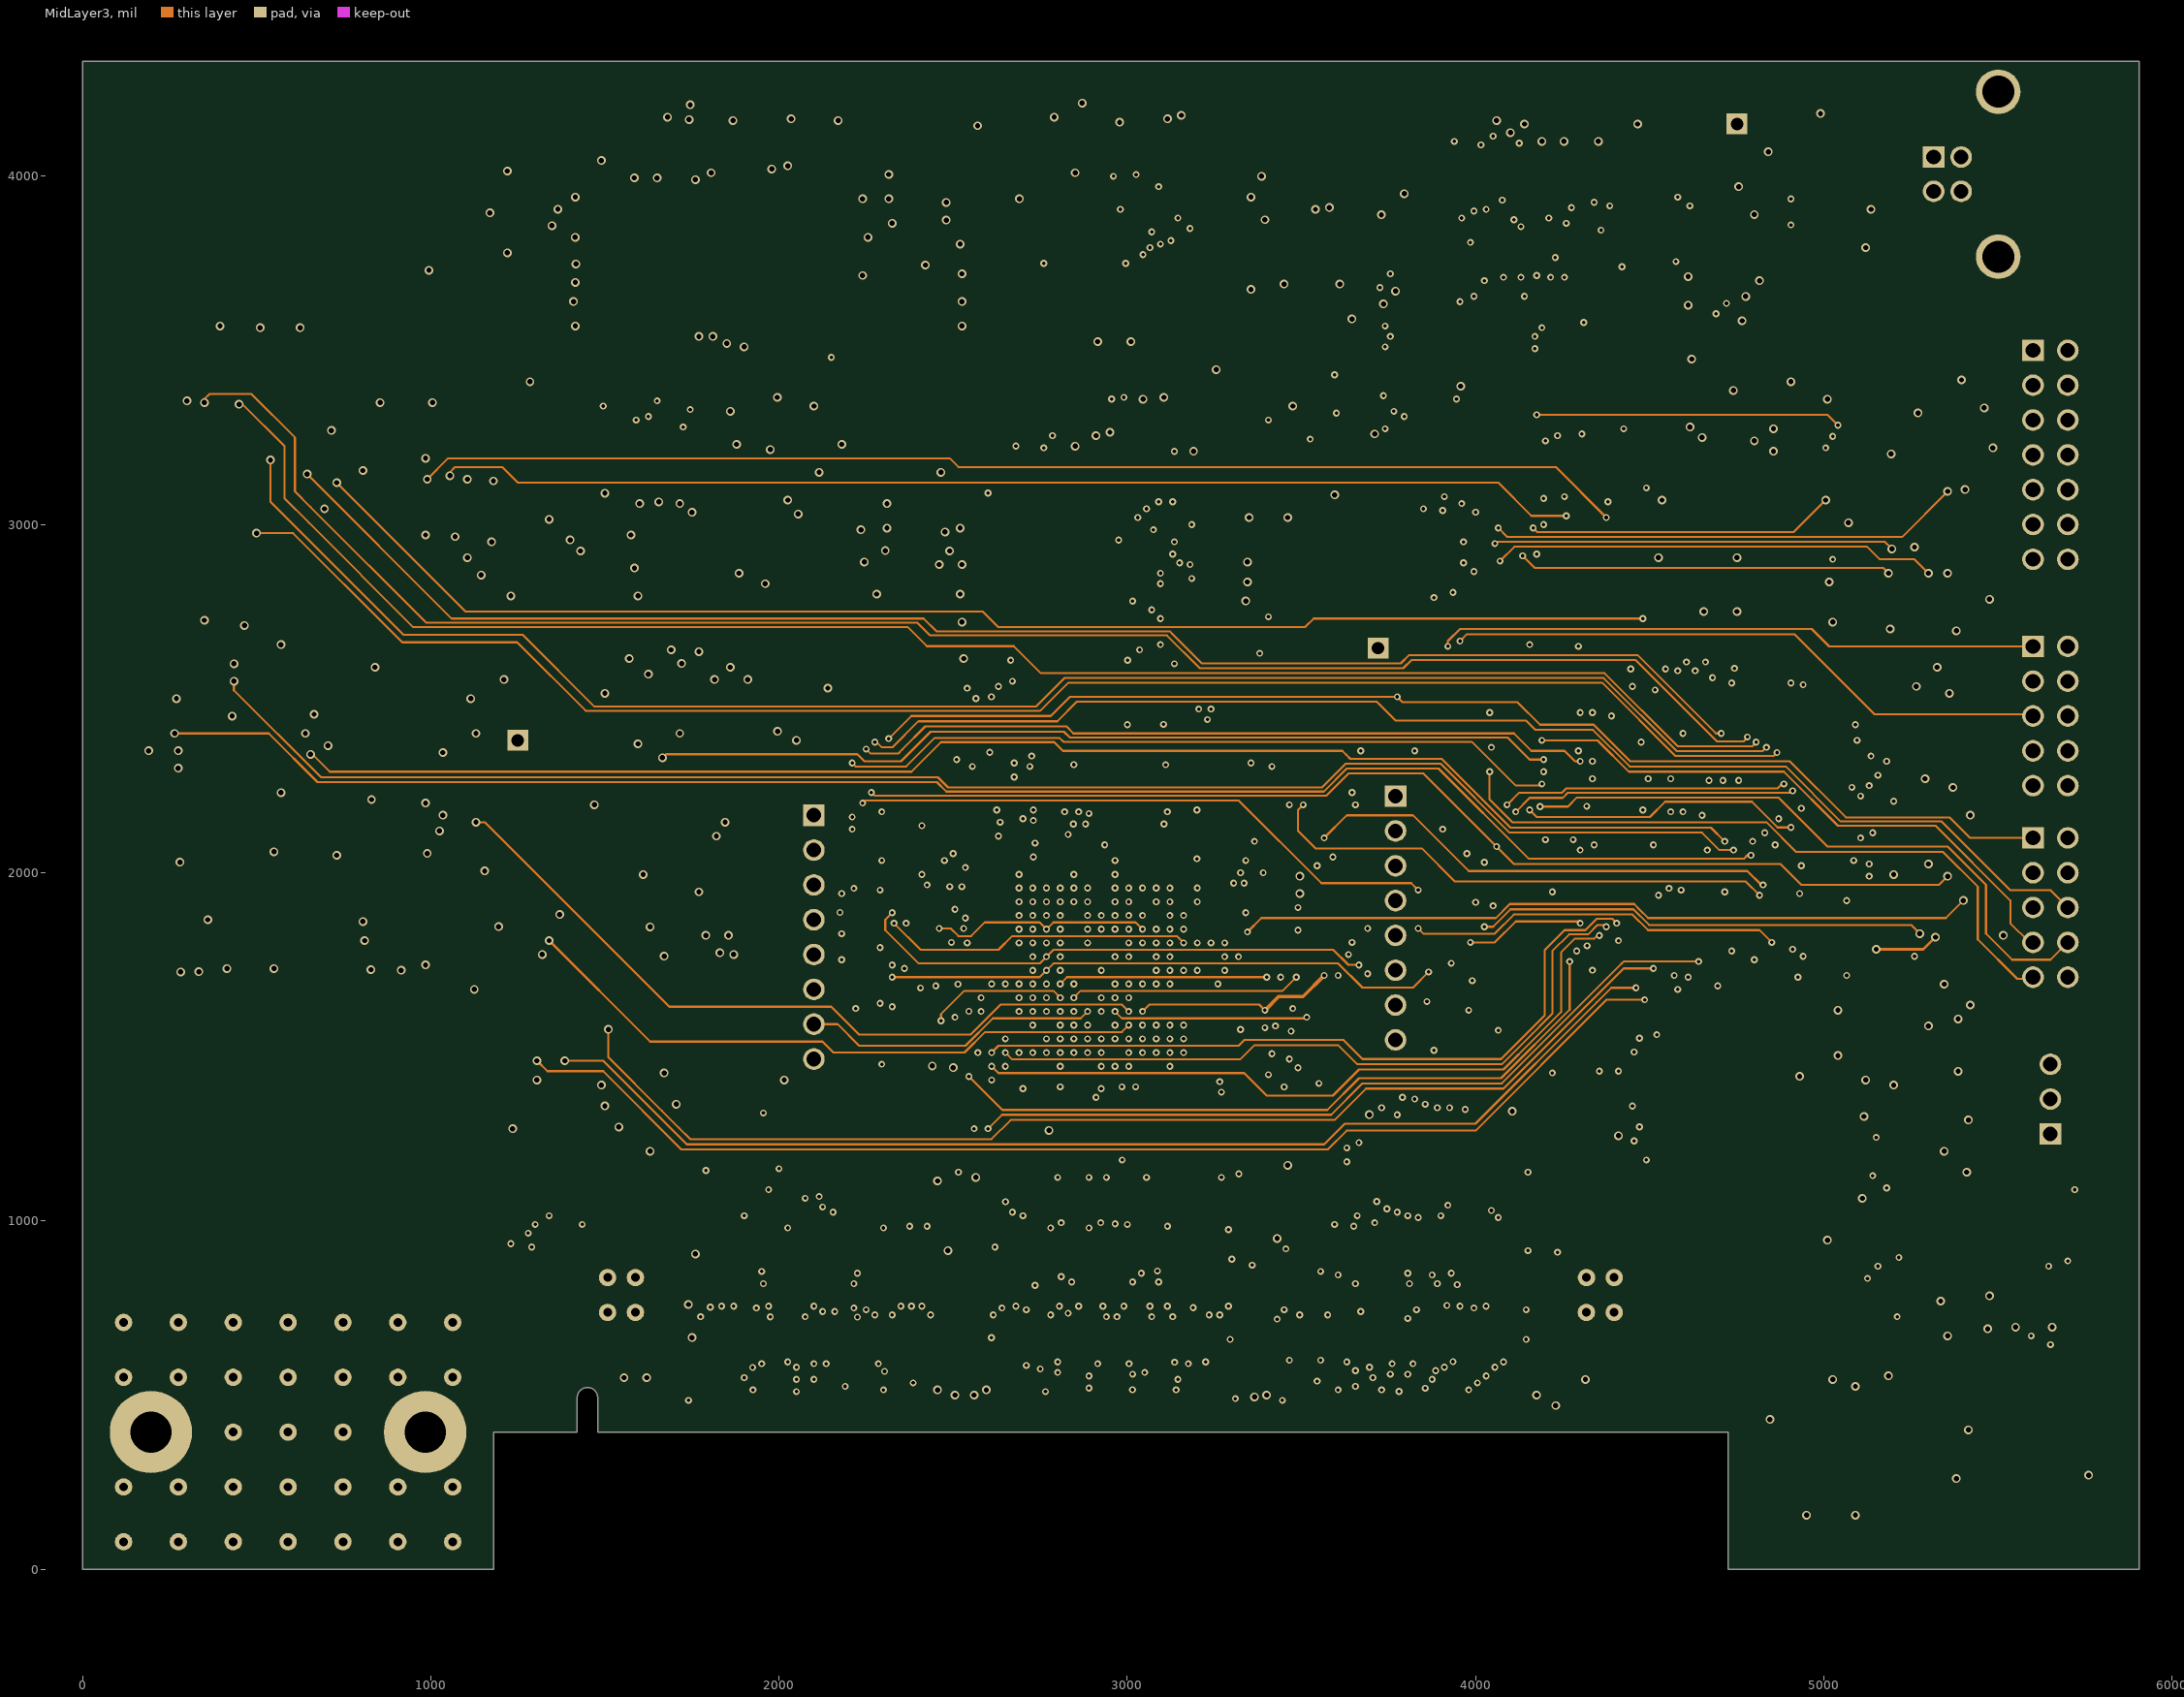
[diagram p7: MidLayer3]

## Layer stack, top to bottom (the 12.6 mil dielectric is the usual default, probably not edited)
Top Layer: signal copper 1.4
Dielectric: core 12.6, FR-4, Dk 4.8
InternalPlane1: plane copper 1.4, net GND
Dielectric: prepreg 12.6, FR-4, Dk 4.8
MidLayer1: signal copper 1.4
Dielectric: core 12.6, FR-4, Dk 4.8
InternalPlane2: plane copper 1.4, net VCC
Dielectric: prepreg 12.6, FR-4, Dk 4.8
MidLayer2: signal copper 1.4
Dielectric: core 12.6, FR-4, Dk 4.8
InternalPlane3: plane copper 1.4, net VCC_1.2V
Dielectric: prepreg 12.6, FR-4, Dk 4.8
MidLayer3: signal copper 1.4
Dielectric: core 12.6, FR-4, Dk 4.8
Bottom Layer: signal copper 1.4

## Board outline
0,0 0,4330.71 5905.51,4330.71 5905.51,0 4724.41,0 4724.41,393.7 1480.31,393.7 1479.51,394.51 1479.51,492.13 ccw(c1449.98,492.13) 1420.45,492.13 1420.45,393.7 1181.1,393.7 1181.1,0

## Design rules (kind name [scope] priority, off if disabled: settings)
AssemblyTestPointUsage [All] p0: scope1count=1 scope1_0_kind=Board scope1_0_value=Board scope2count=1 scope2_0_kind=Board scope2_0_value=Board commentlength=0
AssemblyTestpoint [All] p0: scope1count=1 scope1_0_kind=Board scope1_0_value=Board scope2count=1 scope2_0_kind=Board scope2_0_value=Board commentlength=0
Clearance [All] p0: scope1count=1 scope1_0_kind=Board scope1_0_value=Board scope2count=1 scope2_0_kind=Board scope2_0_value=Board commentlength=0 gap=6
Clearance Clearance_1 [All] p0 off: scope1count=1 scope1_0_kind=Board scope1_0_value=Board scope2count=1 scope2_0_kind=Board scope2_0_value=Board commentlength=67 gap=7 // Protel DXP Scope 1 Expression Was: (InComponentClass('PITCH7'))
Clearance Clearance_2 [All] p0 off: scope1count=1 scope1_0_kind=Board scope1_0_value=Board scope2count=1 scope2_0_kind=Board scope2_0_value=Board commentlength=58 gap=6 // Protel DXP Scope 1 Expression Was: (InComponent('U9'))
Clearance Clearance_2 [(InComponent('U9'))] p1: gap=6
Clearance Clearance_1 [(InComponentClass('PITCH7'))] p2: gap=7
Clearance [All] p3: gap=6
ComponentClearance ComponentClearance_3 [All] p0 off: scope1count=1 scope1_0_kind=Board scope1_0_value=Board scope2count=1 scope2_0_kind=Board scope2_0_value=Board commentlength=83 gap=-10 collisioncheckmode=3 // Protel DXP Scope 1 Expression Was: (HasFootprint('fid') AND InComponent('U11'))
ComponentClearance [All] p0: scope1count=1 scope1_0_kind=Board scope1_0_value=Board scope2count=1 scope2_0_kind=Board scope2_0_value=Board commentlength=0 gap=10 collisioncheckmode=3
ComponentClearance ComponentClearance_1 [All] p0 off: scope1count=1 scope1_0_kind=Board scope1_0_value=Board scope2count=1 scope2_0_kind=Board scope2_0_value=Board commentlength=61 gap=0 collisioncheckmode=3 // Protel DXP Scope 2 Expression Was: (HasFootprint('0805'))
ComponentClearance ComponentClearance_2 [All] p0 off: scope1count=1 scope1_0_kind=Board scope1_0_value=Board scope2count=1 scope2_0_kind=Board scope2_0_value=Board commentlength=61 gap=5 collisioncheckmode=3 // Protel DXP Scope 2 Expression Was: (HasFootprint('0603'))
ComponentClearance ComponentClearance_3 [(HasFootprint('fid') AND InComponent('U11'))] p1: gap=-10 collisioncheckmode=3 verticalgap=10 showdistances=FALSE
ComponentClearance ComponentClearance_2 [(HasFootprint('0603')) vs (HasFootprint('0603'))] p2: gap=5 collisioncheckmode=3 verticalgap=10 showdistances=FALSE
ComponentClearance ComponentClearance_1 [(HasFootprint('0805')) vs (HasFootprint('0805'))] p3: gap=0 collisioncheckmode=3 verticalgap=10 showdistances=FALSE
ComponentClearance [All] p4: gap=10 collisioncheckmode=3 verticalgap=10 showdistances=FALSE
DiffPairsRouting [All] p0: scope1count=1 scope1_0_kind=Board scope1_0_value=Board scope2count=1 scope2_0_kind=Board scope2_0_value=Board commentlength=0
FabricationTestPointUsage [All] p0: scope1count=1 scope1_0_kind=Board scope1_0_value=Board scope2count=1 scope2_0_kind=Board scope2_0_value=Board commentlength=0 valid=0 allowmultiple=FALSE
FabricationTestpoint [All] p0: scope1count=1 scope1_0_kind=Board scope1_0_value=Board scope2count=1 scope2_0_kind=Board scope2_0_value=Board commentlength=0 side=3 testpointundercomponent=TRUE minsize=40 maxsize=100 preferedsize=60 minholesize=0 maxholesize=40 preferedholesize=32 testpointgrid=1
FanoutControl Fanout_BGA [All] p0 off: scope1count=1 scope1_0_kind=Board scope1_0_value=Board scope2count=1 scope2_0_kind=Board scope2_0_value=Board commentlength=69 // Protel DXP Scope 1 Expression Was: IsBGA   Fanout_BGA (Default Rule)
FanoutControl Fanout_LCC [All] p0 off: scope1count=1 scope1_0_kind=Board scope1_0_value=Board scope2count=1 scope2_0_kind=Board scope2_0_value=Board commentlength=69 // Protel DXP Scope 1 Expression Was: IsLCC   Fanout_LCC (Default Rule)
FanoutControl Fanout_SOIC [All] p0 off: scope1count=1 scope1_0_kind=Board scope1_0_value=Board scope2count=1 scope2_0_kind=Board scope2_0_value=Board commentlength=71 // Protel DXP Scope 1 Expression Was: IsSOIC   Fanout_SOIC (Default Rule)
FanoutControl Fanout_Small [All] p0 off: scope1count=1 scope1_0_kind=Board scope1_0_value=Board scope2count=1 scope2_0_kind=Board scope2_0_value=Board commentlength=84 // Protel DXP Scope 1 Expression Was: (CompPinCount < 5)   Fanout_Small (Default Rule)
FanoutControl Fanout_Default [All] p0: scope1count=1 scope1_0_kind=Board scope1_0_value=Board scope2count=1 scope2_0_kind=Board scope2_0_value=Board commentlength=30 // Fanout_Default (Default Rule)
Height [All] p0: scope1count=1 scope1_0_kind=Board scope1_0_value=Board scope2count=1 scope2_0_kind=Board scope2_0_value=Board commentlength=0
HoleSize [All] p0: scope1count=1 scope1_0_kind=Board scope1_0_value=Board scope2count=1 scope2_0_kind=Board scope2_0_value=Board commentlength=0 absolutevalues=TRUE maxlimit=300 minlimit=1 maxpercent=80.000 minpercent=20.000
HoleSize [All] p1: absolutevalues=TRUE maxlimit=300 minlimit=1 maxpercent=80.000 minpercent=20.000
HoleToHoleClearance [All] p0: scope1count=1 scope1_0_kind=Board scope1_0_value=Board scope2count=1 scope2_0_kind=Board scope2_0_value=Board commentlength=0
LayerPairs [All] p0: scope1count=1 scope1_0_kind=Board scope1_0_value=Board scope2count=1 scope2_0_kind=Board scope2_0_value=Board commentlength=0 enforce=TRUE
MinimumSolderMaskSliver [All] p0: scope1count=1 scope1_0_kind=Board scope1_0_value=Board scope2count=1 scope2_0_kind=Board scope2_0_value=Board commentlength=0
NetAntennae [All] p0: scope1count=1 scope1_0_kind=Board scope1_0_value=Board scope2count=1 scope2_0_kind=Board scope2_0_value=Board commentlength=0
PasteMaskExpansion [All] p0: scope1count=1 scope1_0_kind=Board scope1_0_value=Board scope2count=1 scope2_0_kind=Board scope2_0_value=Board commentlength=0 expansion=0
PlaneClearance PlaneClearance_1 [All] p0 off: scope1count=1 scope1_0_kind=Board scope1_0_value=Board scope2count=1 scope2_0_kind=Board scope2_0_value=Board commentlength=44 clearance=10 // Protel DXP Scope 1 Expression Was: isvia
PlaneClearance [All] p0: scope1count=1 scope1_0_kind=Board scope1_0_value=Board scope2count=1 scope2_0_kind=Board scope2_0_value=Board commentlength=0 clearance=20
PlaneClearance PlaneClearance_1 [isvia] p1: clearance=10
PlaneClearance [All] p2: clearance=20
PlaneConnect PlaneConnect_1 [All] p0: scope1count=1 scope1_0_kind=Board scope1_0_value=Board scope2count=1 scope2_0_kind=Board scope2_0_value=Board commentlength=0 planeconnectstyle=Relief reliefexpansion=20 reliefentries=4 reliefconductorwidth=10 reliefairgap=10
PlaneConnect [All] p0 off: scope1count=1 scope1_0_kind=Board scope1_0_value=Board scope2count=1 scope2_0_kind=Board scope2_0_value=Board commentlength=44 planeconnectstyle=Direct reliefexpansion=20 reliefentries=4 reliefconductorwidth=10 reliefairgap=10 // Protel DXP Scope 1 Expression Was: isvia
PlaneConnect [isvia] p1: planeconnectstyle=Direct reliefexpansion=20 reliefentries=4 reliefconductorwidth=10 reliefairgap=10
PlaneConnect PlaneConnect_1 [All] p2: planeconnectstyle=Relief reliefexpansion=20 reliefentries=4 reliefconductorwidth=10 reliefairgap=10
PolygonConnect [All] p0: scope1count=1 scope1_0_kind=Board scope1_0_value=Board scope2count=1 scope2_0_kind=Board scope2_0_value=Board commentlength=0 connectstyle=Relief reliefconductorwidth=50 reliefentries=4 polygonreliefangle="90 Angle"
PolygonConnect [All] p1: connectstyle=Relief reliefconductorwidth=50 reliefentries=4 polygonreliefangle="90 Angle"
RoutingCorners [All] p0: scope1count=1 scope1_0_kind=Board scope1_0_value=Board scope2count=1 scope2_0_kind=Board scope2_0_value=Board commentlength=0 cornerstyle=45-Degree minsetback=100 maxsetback=100
RoutingLayers [All] p0: scope1count=1 scope1_0_kind=Board scope1_0_value=Board scope2count=1 scope2_0_kind=Board scope2_0_value=Board commentlength=0 top layer=Automatic mid layer 1=Automatic mid layer 2=Automatic mid layer 3=Automatic bottom layer=Automatic
RoutingPriority [All] p0: scope1count=1 scope1_0_kind=Board scope1_0_value=Board scope2count=1 scope2_0_kind=Board scope2_0_value=Board commentlength=0
RoutingTopology [All] p0: scope1count=1 scope1_0_kind=Board scope1_0_value=Board scope2count=1 scope2_0_kind=Board scope2_0_value=Board commentlength=0 topology=Shortest
RoutingVias [All] p0: scope1count=1 scope1_0_kind=Board scope1_0_value=Board scope2count=1 scope2_0_kind=Board scope2_0_value=Board commentlength=0 holewidth=15 width=25 viastyle="Through Hole" minholewidth=10 minwidth=20 maxholewidth=28 maxwidth=50
RoutingVias [All] p1: holewidth=15 width=25 viastyle="Through Hole" minholewidth=10 minwidth=20 maxholewidth=28 maxwidth=50
ShortCircuit [All] p0: scope1count=1 scope1_0_kind=Board scope1_0_value=Board scope2count=1 scope2_0_kind=Board scope2_0_value=Board commentlength=0 allowed=FALSE
SilkToSilkClearance [All] p0: scope1count=1 scope1_0_kind=Board scope1_0_value=Board scope2count=1 scope2_0_kind=Board scope2_0_value=Board commentlength=0
SilkscreenOverComponentPads [All] p0: scope1count=1 scope1_0_kind=Board scope1_0_value=Board scope2count=1 scope2_0_kind=Board scope2_0_value=Board commentlength=0
SilkscreenOverComponentPads [All] p1: minsilkscreentomaskgap=10
SolderMaskExpansion [All] p0: scope1count=1 scope1_0_kind=Board scope1_0_value=Board scope2count=1 scope2_0_kind=Board scope2_0_value=Board commentlength=0 expansion=4
SolderMaskExpansion [All] p1: expansion=4
UnRoutedNet [All] p0: scope1count=1 scope1_0_kind=Board scope1_0_value=Board scope2count=1 scope2_0_kind=Board scope2_0_value=Board commentlength=0
Width [All] p0: scope1count=1 scope1_0_kind=Board scope1_0_value=Board scope2count=1 scope2_0_kind=Board scope2_0_value=Board commentlength=0 maxlimit=200 minlimit=6 preferedwidth=8
Width [All] p1: maxlimit=200 minlimit=6 preferedwidth=8
23 further rules are at their usual default settings.

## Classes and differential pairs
component class PITCH7: U11 U13 U29
component class CSU_FPGA_INTERFACE: C10 C11 C12 C14 C21 C23 C29 C33 C36 C46 C49 C54 C63 C71 C75 C76 C77 C78 C81 C82 C83 C84 C85 C86 C87 C88 C89 C90 C91 C92 C93 C94 C95 C96 C97 C98 C99 C100 C101 C102 C103 C104 C105 C106 C107 C109 C111 C114 C115 C116 C117 C118 C119 C120 C121 C122 C123 C124 C125 C126 C127 C128 C129 C130 C131 C132 C133 C134 C135 C136 C137 C140 C141 C142 D3 D4 J1 J2 J3 J5 JP1 JP2 L6 L7 R2 R19 R20 R21 R23 R33 R34 R35 R36 R37 R38 R43 R44 R45 R46 R47 R48 R49 R50 R51 R52 R53 R54 R55 RN1 RN2 TP2 TP3 U1 U9 U10 U13 U17 U22 U24 U25 U26 U27 U30 U32 U33 U44
component class CSU_MP: C1 C2 C3 C4 C5 C6 C7 C8 C9 C13 C15 C16 C17 C18 C19 C20 C22 C24 C25 C26 C27 C28 C30 C31 C32 C34 C35 C37 C38 C39 C40 C41 C42 C43 C44 C45 C47 C48 C50 C51 C52 C53 C55 C56 C57 C58 C59 C60 C61 C62 C64 C65 C66 C67 C68 C69 C70 C72 C73 C74 C79 C80 C108 C110 C112 C113 C138 D1 D2 D5 J4 J6 J8 L1 L2 L3 L4 L5 R1 R3 R4 R5 R6 R7 R8 R9 R10 R11 R12 R13 R14 R15 R16 R17 R18 R22 R24 R25 R26 R27 R28 R29 R30 R31 R32 R39 R40 R41 R42 R56 R57 R58 R59 RN3 RN4 RN5 TP1 U2 U3 U4 U5 U6 U7 U8 U11 U12 U14 U15 U16 U18 U19 U20 U21 U23 U28 U29

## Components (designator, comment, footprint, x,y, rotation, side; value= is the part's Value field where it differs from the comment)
1 "" fid 300,900 r0 top
2 "" fid 5700,140 r0 top
C1 "10uF 6V" "size a" 4360,1360 r180 top
C2 "1uF" 1206 3535,3060 r270 top
C3 "0.1uF" 0603 4410,1485 r180 top
C4 "0.15uF" 0805 5415,780 r270 top
C5 "0.1uF" 0603 5035,4175 r0 top
C6 "0.15uF" 0805 5490,360 r270 top
C7 "0.1uF" 0603 5300,555 r180 top
C8 "1000pF" 0603 4220,1485 r0 top
C9 "0.1uF" 0603 4700,3535 r0 top
C10 "0.1uF" 0603 5415,2590 r90 top
C11 "0.1uF" 0603 3780,2350 r180 top
C12 "0.1uF" 0603 5450,2050 r90 top
C13 "22uF 10V" "Size B" 4910,3525 r90 top
C14 "10pF" 0603 2420,1820 r180 top
C15 "0.1uF" 0603 3995,4150 r180 top
C16 "0.15uF" 0805 5705,360 r270 top
C17 "0.15uF" 0805 5595,360 r270 top
C18 "0.1uF" 0603 3625,3875 r0 top
C19 "0.15uF" 0805 5415,570 r270 top
C20 "0.1uF" 0603 3625,3635 r0 top
C21 "10pF" 0603 2420,1625 r180 top
C22 "0.1uF" 0603 3640,3305 r0 top
C23 "0.1uF" 0603 3930,1700 r270 top
C24 "0.1uF" 0603 5385,1235 r0 top
C25 "0.1uF" 0603 4000,2940 r90 top
C26 "0.1uF" 0603 4760,3270 r180 top
C27 "0.1uF" 0603 4755,3715 r180 top
C28 "0.1uF" 0603 4410,4150 r180 top
C29 "10uF 6V" "size a" 4030,1375 r270 top
C30 "0.1uF" 0603 4200,4150 r0 top
C31 "10uF 6V" "size a" 4375,985 r180 top
C32 "22uF 10V" "Size B" 3680,4000 r180 top
C33 "0.1uF" 0603 3900,915 r90 top
C34 "0.1uF" 0603 5065,1200 r90 top
C35 "0.1uF" 0603 4255,1120 r0 top
C36 "0.1uF" 0603 3611.89,1340.88 r0 top
C37 "0.01uF" 0603 5065,1065 r90 top
C38 "0.01uF" 0603 4410,1120 r90 top
C39 "0.1uF" 0603 4960,3360 r180 top
C40 "22uF 6V" B-Size 1085,3925 r270 top
C41 "22uF 6V" B-Size 1285,3130 r90 top
C42 "0.1uF" 0603 1220,3895 r0 top
C43 "0.1uF" 0603 1230,2935 r0 top
C44 "0.1uF" 0603 1220,3830 r0 top
C45 "0.1uF" 0603 1230,2865 r0 top
C46 "10pF" 0603 2285,1990 r180 top
C47 "0.1uF" 0603 2055,3315.01 r180 top
C48 "0.1uF" 0603 2005,2350 r180 top
C49 "0.1uF" 0603 230,2300 r90 top
C50 "0.1uF" 0603 2420,3795 r180 top
C51 "0.1uF" 0603 2415,2860 r180 top
C52 "0.1uF" 0603 1815,4200 r0 top
C53 "0.1uF" 0603 1820,3270 r0 top
C54 "10pF" 0603 2410,2095 r180 top
C55 "22uF 6V" B-Size 2460,4160 r180 top
C56 "22uF 6V" B-Size 2465,3230 r180 top
C57 "0.1uF" 0603 2365,3865 r0 top
C58 "0.1uF" 0603 2360,2925 r0 top
C59 "0.1uF" 0603 2365,3935 r0 top
C60 "0.1uF" 0603 2360,2990 r0 top
C61 "0.1uF" 0603 2920,4200 r0 top
C62 "0.1uF" 0603 3000,2350 r0 top
C63 "0.1uF" 0603 1155,1770 r90 top
C64 "0.1uF" 0603 3495,3875 r180 top
C65 "0.1uF" 0603 3400,2835 r90 top
C66 "0.1uF" 0603 3045,3305 r0 top
C67 "0.1uF" 0603 2890,3305 r0 top
C68 "0.1uF" 0603 5025,3000 r270 top
C69 "10uF 6V" "size a" 4855,2640 r0 top
C70 "10uF 6V" "size a" 4510,2650 r180 top
C71 "0.1uF" 0603 1155,1895 r90 top
C72 "0.1uF" 0603 4730,2645 r90 top
C73 "0.1uF" 0603 4655,2700 r270 top
C74 "0.1uF" 0603 5300,2370 r270 top
C75 "0.1uF" 0603 1600,1940 r270 top
C76 "0.1uF" 0603 1600,1760 r90 top
C77 "10uF 6V" "size a" 550,1820 r90 top
C78 "10uF 6V" "size a" 990,1820 r90 top
C79 "0.1uF" 0603 4245,2235 r90 top
C80 "0.1uF" 0603 5200,2055 r0 top
C81 "0.1uF" 0603 2850,2215 r90 top
C82 "0.1uF" 0603 2625,2215 r90 top
C83 "0.1uF" 0603 2720,2215 r90 top
C84 "0.1uF" 0603 2915,2215 r90 top
C85 "0.1uF" 0603 3125,2215 r90 top
C86 "0.1uF" 0603 3060,2215 r90 top
C87 "0.1uF" 0603 3395,2040 r0 top
C88 "0.1uF" 0603 3395,1965 r0 top
C89 "0.1uF" 0603 3395,1900 r0 top
C90 "0.1uF" 0603 3395,1765 r0 top
C91 "0.1uF" 0603 3210,1220 r270 top
C92 "0.1uF" 0603 3280,1220 r270 top
C93 "0.1uF" 0603 3095,1220 r270 top
C94 "0.1uF" 0603 3030,1220 r270 top
C95 "0.1uF" 0603 2805,1220 r270 top
C96 "0.1uF" 0603 2740,1220 r270 top
C97 "0.1uF" 0603 2595,1220 r270 top
C98 "0.1uF" 0603 2410,2030 r180 top
C99 "0.1uF" 0603 2420,1490 r180 top
C100 "0.1uF" 0603 4970,545 r180 top
C101 "10uF 6V" "size a" 280,1810 r90 top
C102 "10uF 6V" "size a" 730,1820 r90 top
C103 "0.1uF" 0603 2410,2175 r180 top
C104 "47uF 6V" "Size B" 4950,430 r270 top
C105 "0.1uF" 0603 405,1865 r270 top
C106 "0.1uF" 0603 850,1860 r270 top
C107 "47uF 6V" "Size B" 5090,430 r270 top
C108 "0.1uF" 0603 5390,1670 r0 top
C109 "10uF 6V" "size a" 2565,1050 r270 top
C110 "0.47uF" 0805 4670,1610 r180 top
C111 "10uF 6V" "size a" 3395,1175 r270 top
C112 "10uF 6V" "size a" 4820,1605 r0 top
C113 "0.1uF" 0603 4695,1725 r0 top
C114 "0.1uF" 0603 2995,1720 r0 bottom
C115 "0.1uF" 0603 2635,1740 r0 bottom
C116 "0.1uF" 0603 2895,1740 r180 bottom
C117 "0.1uF" 0603 3040,2075 r90 bottom
C118 "0.1uF" 0603 3215,1759.09 r180 bottom
C119 "0.1uF" 0603 3125,1640 r180 bottom
C120 "0.1uF" 0603 3255,1500 r180 bottom
C121 "0.1uF" 0603 2630,1555 r0 bottom
C122 "0.1uF" 0603 3255,1435 r180 bottom
C123 "0.1uF" 0603 2845,1865 r270 bottom
C124 "0.1uF" 0603 2925,1975 r270 bottom
C125 "0.1uF" 0603 2930,1675 r180 bottom
C126 "10uF 6V" "size a" 2380,1370 r270 top
C127 "10uF 6V" "size a" 3565,1800 r90 top
C128 "0.1uF" 0603 3450,1835 r180 top
C129 "0.1uF" 0603 2973,1805 r180 bottom
C130 "0.1uF" 0603 3450,1660 r180 top
C131 "0.1uF" 0603 3160,1970 r270 bottom
C132 "0.1uF" 0603 2365,1555 r0 top
C133 "0.1uF" 0603 2650,1960 r270 bottom
C134 "0.1uF" 0603 2365,1890 r0 top
C135 "0.1uF" 0603 3040,2010 r0 bottom
C136 "10uF 6V" "size a" 3245,2240 r0 top
C137 "0.1uF" 0603 2000,1310 r90 top
C138 "0.1uF" 0603 5385,1475 r90 top
C140 "0.1uF" 0603 1210,2500 r180 top
C141 "0.1uF" 0603 840,2635 r180 top
C142 "0.1uF" 0603 1545,1335 r90 top
D1 "MMBD914" SOT23A 3655,2845 r0 top (schematic designator D2)
D2 "SML10G4-TR" "LED J-LEAD" 3515,3520 r270 top (schematic designator D3)
D3 "BAT54C-V" BAT54C-V 2365,1760 r270 top
D4 "BAT54C-V" BAT54C-V 2215,2080 r0 top
D5 "SML10G4-TR" "LED J-LEAD" 4360,2800 r0 top
J1 "QMS_EDGE_PWR_PINS" "QMS EDGE PWR PINS" 2952.76,393.7 r90 top locked
J2 "QMSS-078-01-X-D-EM2-PC4" "QMS SMD PWR PINS" 2952.76,787.4 r180 bottom locked
J3 "AMP5103310-01" HEADER5X2 5600,2100 r270 top (schematic designator J6)
J4 "USB_B" "USB_B right angle" 5314.96,4055.12 r90 top (schematic designator J3)
J5 "AMP5103310-01" HEADER5X2 5600,2650 r270 top (schematic designator J6)
J6 "AMP5103310-02" HDR2X7 5600,3500 r270 top
J8 "CON3" "Molex 70543-0002" 5650,1250 r180 top (schematic designator J10)
JP1 "HEADER8X1" HEADER8X1 3770,2220 r90 top (schematic designator JP2)
JP2 "HEADER8X1" HEADER8X1 2100,2165 r90 top
L1 "56uHn" 1812 5260,255 r90 top
L2 "600R" 1206 5075,4070 r180 top
L3 "56uHn" 1812 5105,3715 r270 top
L4 "56uHn" 1812 5535,980 r0 top
L5 "600R" 1206 4175,1215 r0 top
L6 "MSS7341-332NL" MSS7341 4830,765 r90 top
L7 "56uHn" 1812 3585,1650 r270 top
R1 "10K" 0603 3635,3085 r0 top
R2 "24R9" 0603 4245,2360 r90 top
R3 "100K" 0603 3690,3150.01 r180 top
R4 "390R" 0805 3530,3735 r270 top
R5 "22R" 0603 4940,2935 r270 top
R6 "22R" 0603 4940,3060 r90 top
R7 "1K" 0603 3680,3540 r180 top
R8 "1K" 0603 3625,3475 r0 top
R9 "10K" 0603 4755,3920 r180 top
R10 "10K" 0603 3640,3215 r0 top
R11 "1K" 0603 4760,3335 r180 top
R12 "22R" 0603 4225,1670 r270 top
R13 "10K" 0603 5220,770 r90 top
R14 "100K" 0603 5410,1095 r180 top
R15 "36K" 0603 5290,770 r90 top
R16 "22R" 0603 4155,1670 r270 top
R17 "10K" 0603 4700,3845 r0 top
R18 "100K" 0603 5280,1095 r180 top
R19 "220R" 0603 2880.01,1165 r90 top
R20 "330R" 0603 2945,1165 r90 top
R21 "10K" 0603 4040,1700 r270 top
R22 "22R" 0603 4705,3205 r0 top
R23 "100R" 0603 3590,1170 r90 top
R24 "22R" 0603 5065,1405 r270 top
R25 "3K" 0603 1275,3965 r180 top
R26 "3K" 0603 1230,3015 r0 top
R27 "3K" 0603 2365,4005 r0 top
R28 "3K" 0603 2410,3060 r180 top
R29 "390R" 0805 4220,2770 r270 top
R30 "1K" 0603 5230,2315 r90 top
R31 "10K" 0603 5255,2645 r270 top
R32 "100K" 0603 5370,2315 r90 top
R33 "330R" 0805 350,2815 r90 top
R34 "330R" 0805 465,2815 r90 top
R35 "330R" 0805 580,2815 r90 top
R36 "330R" 0805 625,3500 r270 top
R37 "330R" 0805 510,3500 r270 top
R38 "330R" 0805 395,3500 r270 top
R39 "1K02" 0603 5300,2490 r270 top
R40 "1K78" 0603 5230,2435 r90 top
R41 "1K10" 0603 4020,1545 r270 top
R42 "1K02" 0603 3930,1495 r90 top
R43 "22R" 0603 2995,2215 r90 top
R44 "1K0" 0805 1130,2280 r180 top
R45 "150R" 0805 1000,2740 r0 top
R46 "1k0" 0805 855,2735 r180 top
R47 "150R" 0805 880,2270 r180 top
R48 "1K" 0805 1895,1690 r180 top
R49 "1K" 0805 1320,1690 r0 top
R50 "3K0" 0805 1240,1200 r0 top
R51 "3K0" 0805 1445,1200 r0 top
R52 "121R" 0805 1430,1090 r180 top
R53 "3K0" 0805 1700,1200 r0 top
R54 "3K0" 0805 1910,1200 r0 top
R55 "121R" 0805 1900,1090 r180 top
R56 "1K5" 0603 5105,1530 r270 top
R57 "1K5" 0603 4245,2170 r270 top
R58 "1K5" 0603 4245,2050 r270 top
R59 "1K" 0603 5280,1030 r180 top
RN1 "10K" EXB-38VN 2290,1825 r90 top
RN2 "1K" EXB-38VN 2290,1660 r90 top
RN3 "1K" EXB-38Vn 4960,3190 r90 top
RN4 "10K" EXB-38Vn 5395,3255 r90 top
RN5 "1K" EXB-38Vn 5385,1845 r270 top
TP1 "Test point" CON1 4750,4150 r0 top (schematic designator JP1)
TP2 "CON1" CON1 1250,2380 r0 top (schematic designator JP1)
TP3 "Test point" CON1 3720,2645 r0 top (schematic designator JP1)
U1 "EPCS4SI8" SO-8 4115,2300 r180 top (schematic designator U29)
U2 "24MHz, SMT 3.3V" SMT 4635,2925 r0 top (schematic designator U14)
U3 "FIN1002M5" RJ-5 4335,1630 r0 top
U4 "LTC2630A_LM12" SC-70 5245,670 r270 top
U5 "MAX3226ECAE(16-SSOP)" SSOP-16 5520,530 r180 top
U6 "TPS3836K33DBVT" RJ-5 3525,3230 r0 top
U7 "PGB102ST323WR" SOT23 4960,3935 r0 top (schematic designator U12)
U8 "LT6003CS5" RJ-5 5245,1200 r270 top
U9 "EP3C16F256C6" FBGA256-2C 2630,2015 r0 top locked
U10 "74ALVC125-DC" SO-14 4130,1780 r180 top (schematic designator U7)
U11 "CY7C68013A-128AXC" TQFP-128 4495,3220 r180 top
U12 "INA122" SO-8 5055,3140 r90 top (schematic designator U29)
U13 "CDCLVD110ARHBT" S-PVQFN-G32 3810,1170 r0 top (schematic designator U6)
U14 "C5310-D105-SV033-RFL-A1-100" G218B 4930,1130 r90 top
U15 "IDT72V2111L15PF" "TQFP 64" 1490,4000 r0 top (schematic designator U7)
U16 "72V2105" "TQFP 64" 1500,3050 r0 top (schematic designator U7)
U17 "74ALVC125-DC" SO-14 570,2300 r180 top (schematic designator U7)
U18 "IDT72V2111L15PF" "TQFP 64" 2600,4000 r0 top (schematic designator U7)
U19 "72V2105" "TQFP 64" 2600,3050 r0 top (schematic designator U7)
U20 "DS2411R" SOT-23 5250,1500 r270 top
U21 "TPS3836K33DBVT" RJ-5 5270,2175 r180 top
U22 "SN74LVC02A" SO-14 1921.14,1844.57 r180 top (schematic designator U7)
U23 "MC74HC125A" SO-14 5105,2785 r90 top (schematic designator U7)
U24 "74ALVC125-DC" SO-14 805,3050 r90 top (schematic designator U7)
U25 "74ALVC125-DC" SO-14 300,3050 r90 top (schematic designator U7)
U26 "LT1963AEQ#PBF" DDPAK5 550,1600 r180 top (schematic designator U6)
U27 "LT1963AEQ-2.5#PBF" DDPAK5 1050,1600 r180 top (schematic designator U6)
U28 "INA122" SO-8 5300,1900 r270 top (schematic designator U29)
U29 "MSP430F5438" S-PQFP-G100 4940,2465 r0 top
U30 "SN65HVD08" SO-8 1905,1550 r270 top (schematic designator U29)
U32 "INA122" SO-8 1050,2400 r180 top (schematic designator U29)
U33 "INA122" SO-8 1455,1550 r270 top (schematic designator U29)
U44 "74ALVC125-DC" SO-14 1484.96,1844.57 r180 top (schematic designator U7)
? "" fid 300,4100 r0 top

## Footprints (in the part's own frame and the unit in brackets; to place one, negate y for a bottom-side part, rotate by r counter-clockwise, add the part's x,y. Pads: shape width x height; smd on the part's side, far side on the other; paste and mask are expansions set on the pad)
0603 [mil]
  rect 30x30 smd: 1(0,-0.01) 2(55,-0.01)
  silkscreen extent -25,-25 80,25
0805 [mil]
  rect 60x50 smd: 1(0,0) 2(90,0)
  silkscreen extent -50,-45 140,45
1206 [mil]
  rect 60x60 smd: 1(0,0) 2(135,0)
  silkscreen extent -50,-50 185,50
1812 [mil]
  rect 60x125 smd: 1(0.12,-0.04) 2(185.12,-0.04)
  silkscreen extent -50,-85 235,85
B-Size [mil]
  rect 95x100 smd: 1(0,0) 2(190,0)
  silkscreen extent -70,-60 250,60
BAT54C-V [mil]
  rect 30x37 smd: 1(0,0) 2(74.8,0) 3(37.4,78.74)
  silkscreen extent -14,34 89,90
CON1 [mil]
  rect 60x60 hole 36: 1(0,0)
  silkscreen extent -45,-45 45,45
DDPAK5 [mil]
  rect 40x160 smd: 1(0,-0.29) 2(67,-0.29) 3(134,-0.29) 4(201,-0.29) 5(268,-0.29)
  rect 330x370 smd: ""(130,339.72)
  silkscreen extent -50,150 310,540
EXB-38VN [mil]
  rect 17x28 smd: 1(0,-0.01) 2(31.5,-0.01) 3(62.99,-0.01) 4(94.49,-0.01) 5(94.49,68) 6(62.99,68) 7(31.5,68) 8(0,68)
  silkscreen extent -20,-28 120,93
EXB-38Vn [mil]
  rect 17x28 smd: 1(0,-0.01) 2(31.5,-0.01) 3(62.99,-0.01) 4(94.49,-0.01) 5(94.49,68) 6(62.99,68) 7(31.5,68) 8(0,68)
  silkscreen extent -20,-28 120,93
FBGA256-2C [mm] "256-Ball FineLine Ball Grid Array (FBGA256) - Option 1"
  round 0.47 smd: A1(0,0) A2(1,0) A3(2,0) A4(3,0) A5(4,0) A6(5,0) A7(6,0) A8(7,0) A9(8,0) A10(9,0) A11(10,0) A12(11,0) A13(12,0) A14(13,0) A15(14,0) A16(15,0) B1(0,-1) B2(1,-1) B3(2,-1) B4(3,-1) B5(4,-1) B6(5,-1) B7(6,-1) B8(7,-1) B9(8,-1) B10(9,-1) B11(10,-1) B12(11,-1) B13(12,-1) B14(13,-1) B15(14,-1) B16(15,-1) C1(0,-2) C2(1,-2) C3(2,-2) C4(3,-2) C5(4,-2) C6(5,-2) C7(6,-2) C8(7,-2) C9(8,-2) C10(9,-2) C11(10,-2) C12(11,-2) C13(12,-2) C14(13,-2) C15(14,-2) C16(15,-2) D1(0,-3) D2(1,-3) D3(2,-3) D4(3,-3) D5(4,-3) D6(5,-3) D7(6,-3) D8(7,-3) D9(8,-3) D10(9,-3) D11(10,-3) D12(11,-3) D13(12,-3) D14(13,-3) D15(14,-3) D16(15,-3) E1(0,-4) E2(1,-4) E3(2,-4) E4(3,-4) E5(4,-4) E6(5,-4) E7(6,-4) E8(7,-4) E9(8,-4) E10(9,-4) E11(10,-4) E12(11,-4) E13(12,-4) E14(13,-4) E15(14,-4) E16(15,-4) F1(0,-5) F2(1,-5) F3(2,-5) F4(3,-5) F5(4,-5) F6(5,-5) F7(6,-5) F8(7,-5) F9(8,-5) F10(9,-5) F11(10,-5) F12(11,-5) F13(12,-5) F14(13,-5) F15(14,-5) F16(15,-5) G1(0,-6) G2(1,-6) G3(2,-6) G4(3,-6) G5(4,-6) G6(5,-6) G7(6,-6) G8(7,-6) G9(8,-6) G10(9,-6) G11(10,-6) G12(11,-6) G13(12,-6) G14(13,-6) G15(14,-6) G16(15,-6) H1(0,-7) H2(1,-7) H3(2,-7) H4(3,-7) H5(4,-7) H6(5,-7) H7(6,-7) H8(7,-7) H9(8,-7) H10(9,-7) H11(10,-7) H12(11,-7) H13(12,-7) H14(13,-7) H15(14,-7) H16(15,-7) J1(0,-8) J2(1,-8) J3(2,-8) J4(3,-8) J5(4,-8) J6(5,-8) J7(6,-8) J8(7,-8) J9(8,-8) J10(9,-8) J11(10,-8) J12(11,-8) J13(12,-8) J14(13,-8) J15(14,-8) J16(15,-8) K1(0,-9) K2(1,-9) K3(2,-9) K4(3,-9) K5(4,-9) K6(5,-9) K7(6,-9) K8(7,-9) K9(8,-9) K10(9,-9) K11(10,-9) K12(11,-9) K13(12,-9) K14(13,-9) K15(14,-9) K16(15,-9) L1(0,-10) L2(1,-10) L3(2,-10) L4(3,-10) L5(4,-10) L6(5,-10) L7(6,-10) L8(7,-10) L9(8,-10) L10(9,-10) L11(10,-10) L12(11,-10) L13(12,-10) L14(13,-10) L15(14,-10) L16(15,-10) M1(0,-11) M2(1,-11) M3(2,-11) M4(3,-11) M5(4,-11) M6(5,-11) M7(6,-11) M8(7,-11) M9(8,-11) M10(9,-11) M11(10,-11) M12(11,-11) M13(12,-11) M14(13,-11) M15(14,-11) M16(15,-11) N1(0,-12) N2(1,-12) N3(2,-12) N4(3,-12) N5(4,-12) N6(5,-12) N7(6,-12) N8(7,-12) N9(8,-12) N10(9,-12) N11(10,-12) N12(11,-12) N13(12,-12) N14(13,-12) N15(14,-12) N16(15,-12) P1(0,-13) P2(1,-13) P3(2,-13) P4(3,-13) P5(4,-13) P6(5,-13) P7(6,-13) P8(7,-13) P9(8,-13) P10(9,-13) P11(10,-13) P12(11,-13) P13(12,-13) P14(13,-13) P15(14,-13) P16(15,-13) R1(0,-14) R2(1,-14) R3(2,-14) R4(3,-14) R5(4,-14) R6(5,-14) R7(6,-14) R8(7,-14) R9(8,-14) R10(9,-14) R11(10,-14) R12(11,-14) R13(12,-14) R14(13,-14) R15(14,-14) R16(15,-14) T1(0,-15) T2(1,-15) T3(2,-15) T4(3,-15) T5(4,-15) T6(5,-15) T7(6,-15) T8(7,-15) T9(8,-15) T10(9,-15) T11(10,-15) T12(11,-15) T13(12,-15) T14(13,-15) T15(14,-15) T16(15,-15)
  silkscreen extent -1.77,-16 16,1
fid [mil]
  round 40 smd: ""(0,0)
G218B [mil]
  rect 51.18x98.43 smd: 1(0,0)
  rect 52x100 smd: 2(100,0) 3(200,0) 4(200,342.52) 5(100,342.52) 6(0,342.52)
  silkscreen extent -183,-26 383,368
HDR2X7 [mil] "Connector; Header; 7x2 Position"
  rect 62x62 hole 42: 1(0,0)
  round 62 hole 42: 2(0,100) 3(100,0) 4(100,100) 5(200,0) 6(200,100) 7(300,0) 8(300,100) 9(400,0) 10(400,100) 11(500,0) 12(500,100) 13(600,0) 14(600,100)
  silkscreen extent -50,-50 650,150
HEADER5X2 [mil]
  rect 62x62 hole 42: 1(0,0)
  round 62 hole 42: 2(0,100) 3(100,0) 4(100,100) 5(200,0) 6(200,100) 7(300,0) 8(300,100) 9(400,0) 10(400,100)
  silkscreen extent -50,-50 450,150
HEADER8X1 [mil]
  rect 62x62 hole 42: 1(0,0)
  round 62 hole 42: 2(-100,0) 3(-200,0) 4(-300,0) 5(-400,0) 6(-500,0) 7(-600,0) 8(-700,0)
  silkscreen extent -750,-50 50,50
"LED J-LEAD" [mm]
  rect 1.6x1.6 smd: A(0,0) K(3.04,0)
  silkscreen extent -1.3,-1.6 4.34,1.6
"Molex 70543-0002" [mil]
  rect 62x62 hole 42: 1(0,0)
  round 62 hole 42: 2(0,-100) 3(0,-200)
  silkscreen extent -150,-300 100,100
MSS7341 [mil]
  rect 280x100 smd: 1(0,0) 2(0,-181)
  silkscreen extent -150,-240 150,60
"QMS EDGE PWR PINS" [mil] "78 pos (156 pin) + 8 pwr pins"
  rect 60x14 smd: 1(69.15,-1152.45) 3(69.15,-1127.45) 5(69.15,-1102.45) 7(69.15,-1077.45) 9(69.15,-1052.45) 11(69.15,-1027.45) 13(69.15,-1002.45) 15(69.15,-977.45) 17(69.15,-952.45) 19(69.15,-927.45) 21(69.15,-902.45) 23(69.15,-877.45) 25(69.15,-852.45) 27(69.15,-827.45) 29(69.15,-802.45) 31(69.15,-777.45) 33(69.15,-752.45) 35(69.15,-727.45) 37(69.15,-702.45) 39(69.15,-677.45) 41(69.15,-652.45) 43(69.15,-627.45) 45(69.15,-602.45) 47(69.15,-577.45) 49(69.15,-552.45) 51(69.15,-527.45) 53(68.09,-312.11) 55(68.09,-287.11) 57(68.09,-262.11) 59(68.09,-237.11) 61(68.09,-212.11) 63(68.09,-187.11) 65(68.09,-162.11) 67(68.09,-137.11) 69(68.09,-112.11) 71(68.09,-87.11) 73(68.09,-62.11) 75(68.09,-37.11) 77(68.09,-12.11) 79(68.09,12.89) 81(68.09,37.89) 83(68.09,62.89) 85(68.09,87.89) 87(68.09,112.89) 89(68.09,137.89) 91(68.09,162.89) 93(68.09,187.89) 95(68.09,212.89) 97(68.09,237.89) 99(68.09,262.89) 101(68.09,287.89) 103(68.09,312.89) 105(68.09,528.05) 107(68.09,553.05) 109(68.09,578.05) 111(68.09,603.05) 113(68.09,628.05) 115(68.09,653.05) 117(68.09,678.05) 119(68.09,703.05) 121(68.09,728.05) 123(68.09,753.05) 125(68.09,778.05) 127(68.09,803.05) 129(68.09,828.05) 131(68.09,853.05) 133(68.09,878.05) 135(68.09,903.05) 137(68.09,928.05) 139(68.09,953.05) 141(68.09,978.05) 143(68.09,1003.05) 145(68.09,1028.05) 147(68.09,1053.05) 149(68.09,1078.05) 151(68.09,1103.05) 153(68.09,1128.05) 155(68.09,1153.05)
  rect 60x14 smd far side: 2(69.15,-1152.45) 4(69.15,-1127.45) 6(69.15,-1102.45) 8(69.15,-1077.45) 10(69.15,-1052.45) 12(69.15,-1027.45) 14(69.15,-1002.45) 16(69.15,-977.45) 18(69.15,-952.45) 20(69.15,-927.45) 22(69.15,-902.45) 24(69.15,-877.45) 26(69.15,-852.45) 28(69.15,-827.45) 30(69.15,-802.45) 32(69.15,-777.45) 34(69.15,-752.45) 36(69.15,-727.45) 38(69.15,-702.45) 40(69.15,-677.45) 42(69.15,-652.45) 44(69.15,-627.45) 46(69.15,-602.45) 48(69.15,-577.45) 50(69.15,-552.45) 52(69.15,-527.45) 54(68.09,-312.11) 56(68.09,-287.11) 58(68.09,-262.11) 60(68.09,-237.11) 62(68.09,-212.11) 64(68.09,-187.11) 66(68.09,-162.11) 68(68.09,-137.11) 70(68.09,-112.11) 72(68.09,-87.11) 74(68.09,-62.11) 76(68.09,-37.11) 78(68.09,-12.11) 80(68.09,12.89) 82(68.09,37.89) 84(68.09,62.89) 86(68.09,87.89) 88(68.09,112.89) 90(68.09,137.89) 92(68.09,162.89) 94(68.09,187.89) 96(68.09,212.89) 98(68.09,237.89) 100(68.09,262.89) 102(68.09,287.89) 104(68.09,312.89) 106(68.09,528.05) 108(68.09,553.05) 110(68.09,578.05) 112(68.09,603.05) 114(68.09,628.05) 116(68.09,653.05) 118(68.09,678.05) 120(68.09,703.05) 122(68.09,728.05) 124(68.09,753.05) 126(68.09,778.05) 128(68.09,803.05) 130(68.09,828.05) 132(68.09,853.05) 134(68.09,878.05) 136(68.09,903.05) 138(68.09,928.05) 140(68.09,953.05) 142(68.09,978.05) 144(68.09,1003.05) 146(68.09,1028.05) 148(68.09,1053.05) 150(68.09,1078.05) 152(68.09,1103.05) 154(68.09,1128.05) 156(68.09,1153.05)
  rect 60x31 smd far side: 157(41.09,1230.55) 158(41.09,490.55) 159(41.09,390.55) 160(41.09,-349.45) 161(41.09,-449.45) 162(41.09,-1189.45)
  rect 60x31 smd: 157(41.09,1190.55) 158(41.09,450.55) 159(41.09,350.55) 161(41.09,-489.45) 162(41.09,-1229.45) 163(41.09,-389.45)
  rect 100x30 smd: PC01(59.65,-1444.45) PC03(59.65,-1365.55) PC05(59.15,1365.55) PC07(59.15,1444.45)
  rect 100x30 smd far side: PC02(59.65,-1444.45) PC04(59.65,-1365.55) PC06(59.15,1365.55) PC08(59.15,1444.45)
  silkscreen extent -373,-1649 217,1647
"QMS SMD PWR PINS" [mm] "78 pos (156 pin) + 8 pwr pins"
  rect 0.4x2.15 smd: 1(-29.28,-3.24) 2(-29.28,3.24) 3(-28.645,-3.24) 4(-28.645,3.24) 5(-28.01,-3.24) 6(-28.01,3.24) 7(-27.375,-3.24) 8(-27.375,3.24) 9(-26.74,-3.24) 10(-26.74,3.24) 11(-26.105,-3.24) 12(-26.105,3.24) 13(-25.47,-3.24) 14(-25.47,3.24) 15(-24.835,-3.24) 16(-24.835,3.24) 17(-24.2,-3.24) 18(-24.2,3.24) 19(-23.565,-3.24) 20(-23.565,3.24) 21(-22.93,-3.24) 22(-22.93,3.24) 23(-22.295,-3.24) 24(-22.295,3.24) 25(-21.66,-3.24) 26(-21.66,3.24) 27(-21.025,-3.24) 28(-21.025,3.24) 29(-20.39,-3.24) 30(-20.39,3.24) 31(-19.755,-3.24) 32(-19.755,3.24) 33(-19.12,-3.24) 34(-19.12,3.24) 35(-18.485,-3.24) 36(-18.485,3.24) 37(-17.85,-3.24) 38(-17.85,3.24) 39(-17.215,-3.24) 40(-17.215,3.24) 41(-16.58,-3.24) 42(-16.58,3.24) 43(-15.945,-3.24) 44(-15.945,3.24) 45(-15.31,-3.24) 46(-15.31,3.24) 47(-14.675,-3.24) 48(-14.675,3.24) 49(-14.04,-3.24) 50(-14.04,3.24) 51(-13.405,-3.24) 52(-13.405,3.24) 53(-7.94,-3.24) 54(-7.94,3.24) 55(-7.305,-3.24) 56(-7.305,3.24) 57(-6.67,-3.24) 58(-6.67,3.24) 59(-6.035,-3.24) 60(-6.035,3.24) 61(-5.4,-3.24) 62(-5.4,3.24) 63(-4.765,-3.24) 64(-4.765,3.24) 65(-4.13,-3.24) 66(-4.13,3.24) 67(-3.495,-3.24) 68(-3.495,3.24) 69(-2.86,-3.24) 70(-2.86,3.24) 71(-2.225,-3.24) 72(-2.225,3.24) 73(-1.59,-3.24) 74(-1.59,3.24) 75(-0.955,-3.24) 76(-0.955,3.24) 77(-0.32,-3.24) 78(-0.32,3.24) 79(0.315,-3.24) 80(0.315,3.24) 81(0.95,-3.24) 82(0.95,3.24) 83(1.585,-3.24) 84(1.585,3.24) 85(2.22,-3.24) 86(2.22,3.24) 87(2.855,-3.24) 88(2.855,3.24) 89(3.49,-3.24) 90(3.49,3.24) 91(4.125,-3.24) 92(4.125,3.24) 93(4.76,-3.24) 94(4.76,3.24) 95(5.395,-3.24) 96(5.395,3.24) 97(6.03,-3.24) 98(6.03,3.24) 99(6.665,-3.24) 100(6.665,3.24) 101(7.3,-3.24) 102(7.3,3.24) 103(7.935,-3.24) 104(7.935,3.24) 105(13.4,-3.24) 106(13.4,3.24) 107(14.035,-3.24) 108(14.035,3.24) 109(14.67,-3.24) 110(14.67,3.24) 111(15.305,-3.24) 112(15.305,3.24) 113(15.94,-3.24) 114(15.94,3.24) 115(16.575,-3.24) 116(16.575,3.24) 117(17.21,-3.24) 118(17.21,3.24) 119(17.845,-3.24) 120(17.845,3.24) 121(18.48,-3.24) 122(18.48,3.24) 123(19.115,-3.24) 124(19.115,3.24) 125(19.75,-3.24) 126(19.75,3.24) 127(20.385,-3.24) 128(20.385,3.24) 129(21.02,-3.24) 130(21.02,3.24) 131(21.655,-3.24) 132(21.655,3.24) 133(22.29,-3.24) 134(22.29,3.24) 135(22.925,-3.24) 136(22.925,3.24) 137(23.56,-3.24) 138(23.56,3.24) 139(24.195,-3.24) 140(24.195,3.24) 141(24.83,-3.24) 142(24.83,3.24) 143(25.465,-3.24) 144(25.465,3.24) 145(26.1,-3.24) 146(26.1,3.24) 147(26.735,-3.24) 148(26.735,3.24) 149(27.37,-3.24) 150(27.37,3.24) 151(28.005,-3.24) 152(28.005,3.24) 153(28.64,-3.24) 154(28.64,3.24) 155(29.275,-3.24) 156(29.275,3.24)
  rect 17.958x0.5 smd: 157(-21.34,0) 158(0,0) 159(21.34,0)
  round 1.27 hole 0.635: PC01(-36.703,-1.27) PC02(-36.703,1.27) PC03(-34.671,-1.27) PC04(-34.684,1.27) PC05(34.671,-1.27) PC06(34.671,1.27) PC07(36.703,-1.27) PC08(36.703,1.27)
  silkscreen extent -38.16,-4.65 38.15,4.32
RJ-5 [mm] "SOT-23/SC-74A; 5 Leads; Body 3.1 x 3 mm, inc. leads (LxW max)"
  rect 0.55x1.45 smd: 1(-0.95,-1.075) 2(0,-1.075) 3(0.95,-1.075) 4(0.95,1.075) 5(-0.95,1.075)
  silkscreen extent -1.57,-1.35 1.55,0.9
S-PQFP-G100 [mm]
  oval 0.3x1.8 smd: 1(0,0) 2(-0.5,0) 3(-1,0) 4(-1.5,0) 5(-2,0) 6(-2.5,0) 7(-3,0) 8(-3.5,0) 9(-4,0) 10(-4.5,0) 11(-5,0) 12(-5.5,0) 13(-6,0) 14(-6.5,0) 15(-7,0) 16(-7.5,0) 17(-8,0) 18(-8.5,0) 19(-9,0) 20(-9.5,0) 21(-10,0) 22(-10.5,0) 23(-11,0) 24(-11.5,0) 25(-12,0) 51(-12,-15.1) 52(-11.5,-15.1) 53(-11,-15.1) 54(-10.5,-15.1) 55(-10,-15.1) 56(-9.5,-15.1) 57(-9,-15.1) 58(-8.5,-15.1) 59(-8,-15.1) 60(-7.5,-15.1) 61(-7,-15.1) 62(-6.5,-15.1) 63(-6,-15.1) 64(-5.5,-15.1) 65(-5,-15.1) 66(-4.5,-15.1) 67(-4,-15.1) 68(-3.5,-15.1) 69(-3,-15.1) 70(-2.5,-15.1) 71(-2,-15.1) 72(-1.5,-15.1) 73(-1,-15.1) 74(-0.5,-15.1) 75(0,-15.1)
  oval 1.8x0.3 smd: 26(-13.55,-1.55) 27(-13.55,-2.05) 28(-13.55,-2.55) 29(-13.55,-3.05) 30(-13.55,-3.55) 31(-13.55,-4.05) 32(-13.55,-4.55) 33(-13.55,-5.05) 34(-13.55,-5.55) 35(-13.55,-6.05) 36(-13.55,-6.55) 37(-13.55,-7.05) 38(-13.55,-7.55) 39(-13.55,-8.05) 40(-13.55,-8.55) 41(-13.55,-9.05) 42(-13.55,-9.55) 43(-13.55,-10.05) 44(-13.55,-10.55) 45(-13.55,-11.05) 46(-13.55,-11.55) 47(-13.55,-12.05) 48(-13.55,-12.55) 49(-13.55,-13.05) 50(-13.55,-13.55) 76(1.55,-13.55) 77(1.55,-13.05) 78(1.55,-12.55) 79(1.55,-12.05) 80(1.55,-11.55) 81(1.55,-11.05) 82(1.55,-10.55) 83(1.55,-10.05) 84(1.55,-9.55) 85(1.55,-9.05) 86(1.55,-8.55) 87(1.55,-8.05) 88(1.55,-7.55) 89(1.55,-7.05) 90(1.55,-6.55) 91(1.55,-6.05) 92(1.55,-5.55) 93(1.55,-5.05) 94(1.55,-4.55) 95(1.55,-4.05) 96(1.55,-3.55) 97(1.55,-3.05) 98(1.55,-2.55) 99(1.55,-2.05) 100(1.55,-1.55)
  silkscreen extent -12.25,-13.8 0.82,0.12
S-PVQFN-G32 [mm]
  rect 0.5x0.3 smd: 1(-2.35,1.75) 2(-2.35,1.25) 3(-2.35,0.75) 4(-2.35,0.25) 5(-2.35,-0.25) 6(-2.35,-0.75) 7(-2.35,-1.25) 8(-2.35,-1.75) 17(2.35,-1.75) 18(2.35,-1.25) 19(2.35,-0.75) 20(2.35,-0.25) 21(2.35,0.25) 22(2.35,0.75) 23(2.35,1.25) 24(2.35,1.75)
  rect 0.3x0.5 smd: 9(-1.75,-2.35) 10(-1.25,-2.35) 11(-0.75,-2.35) 12(-0.25,-2.35) 13(0.25,-2.35) 14(0.75,-2.35) 15(1.25,-2.35) 16(1.75,-2.35) 25(1.75,2.35) 26(1.25,2.35) 27(0.75,2.35) 28(0.25,2.35) 29(-0.25,2.35) 30(-0.75,2.35) 31(-1.25,2.35) 32(-1.75,2.35)
  rect 3.25x3.25 smd: T_PAD(0,0)
  silkscreen extent -2.78,-2.78 2.78,2.8
SC-70 [mm] "SOT-353/SC-88A; 5 Leads; Body 2.2 x 2.4 mm, inc. leads (LxW max)"
  rect 0.35x1.15 smd: 1(-0.65,-0.875) 2(0,-0.875) 3(0.65,-0.875) 4(0.65,0.875) 5(0,0.875) 6(-0.65,0.875)
  silkscreen extent -1.15,-2.16 1.15,0.7
"size a" [mil]
  rect 85x71 smd: 1(0,0) 2(138,0)
  silkscreen extent -70,-65 220,65
"Size B" [mil]
  rect 95x100 smd: 1(-0.15,-0.22) 2(189.85,-0.22)
  silkscreen extent -70,-60 250,60
SMT [mil]
  rect 70x78 smd: 1(-0.06,0) 2(199.94,0) 3(199.94,165) 4(-0.06,165)
  silkscreen extent -60,-60 260,220
SO-8 [mil]
  oval 80x24 smd: 1(0,0) 2(0,-50) 3(0,-100) 4(0,-150) 5(220,-150) 6(220,-100) 7(220,-50) 8(220,0)
  silkscreen extent 60,-175 160,25
SO-14 [mil]
  oval 80x24 smd: 1(0,0) 2(0,-50) 3(0,-100) 4(0,-150) 5(0,-200) 6(0,-250) 7(0,-300) 8(220,-300) 9(220,-250) 10(220,-200) 11(220,-150) 12(220,-100) 13(220,-50) 14(220,0)
  silkscreen extent 60,-325 160,25
SOT23 [mm]
  rect 0.95x0.9 smd: 1(0,0) 2(0,-1.9) 3(2.5,-0.95)
  silkscreen extent 0.87,-2.25 2.5,0.35
SOT23A [mm]
  rect 0.9x0.95 smd: 1(0,0) 2(1.9,0) 3(0.95,2.35)
  silkscreen extent -0.35,0.87 2.25,2.35
SOT-23 [mm]
  rect 0.9x0.95 smd: 1(-0.95,-1.25) 2(0.95,-1.25) 3(0,1.25)
  silkscreen extent -1.3,-0.38 1.3,1.25
SSOP-16 [mil]
  rect 15x100 smd: 1(0,0)
  oval 15x100 smd: 2(-25.59,0) 3(-51.18,0) 4(-76.77,0) 5(-102.36,0) 6(-127.95,0) 7(-153.54,0) 8(-179.13,0) 9(-179.13,-255) 10(-153.54,-255) 11(-127.95,-255) 12(-102.36,-255) 13(-76.77,-255) 14(-51.18,-255) 15(-25.59,-255) 16(0,-255)
  silkscreen extent -179,-195 5,85
"TQFP 64" [mm]
  rect 1.905x0.5 smd: 1(0,0) 2(0,-0.8) 3(0,-1.6) 4(0,-2.4) 5(0,-3.2) 6(0,-4) 7(0,-4.8) 8(0,-5.6) 9(0,-6.4) 10(0,-7.2) 11(0,-8) 12(0,-8.8) 13(0,-9.6) 14(0,-10.4) 15(0,-11.2) 16(0,-12) 33(16.713,-12) 34(16.713,-11.2) 35(16.713,-10.4) 36(16.713,-9.6) 37(16.713,-8.8) 38(16.713,-8) 39(16.713,-7.2) 40(16.713,-6.4) 41(16.713,-5.6) 42(16.713,-4.8) 43(16.713,-4) 44(16.713,-3.2) 45(16.713,-2.4) 46(16.713,-1.6) 47(16.713,-0.8) 48(16.713,0)
  rect 0.5x1.905 smd: 17(2.4,-14.326) 18(3.2,-14.326) 19(4,-14.326) 20(4.8,-14.326) 21(5.6,-14.326) 22(6.4,-14.326) 23(7.2,-14.326) 24(8,-14.326) 25(8.8,-14.326) 26(9.6,-14.326) 27(10.4,-14.326) 28(11.2,-14.326) 29(12,-14.326) 30(12.8,-14.326) 31(13.6,-14.326) 32(14.4,-14.326) 49(14.4,2.362) 50(13.6,2.362) 51(12.8,2.362) 52(12,2.362) 53(11.2,2.362) 54(10.4,2.362) 55(9.6,2.362) 56(8.8,2.362) 57(8,2.362) 58(7.2,2.362) 59(6.4,2.362) 60(5.6,2.362) 61(4.8,2.362) 62(4,2.362) 63(3.2,2.362) 64(2.4,2.362)
  silkscreen extent -0.51,-14.73 17.02,2.79
TQFP-128 [mm]
  rect 2.286x0.3 smd: 1(0,0) 2(0,-0.5) 3(0,-1) 4(0,-1.5) 5(0,-2) 6(0,-2.5) 7(0,-3) 8(0,-3.5) 9(0,-4) 10(0,-4.5) 11(0,-5) 12(0,-5.5) 13(0,-6) 14(0,-6.5) 15(0,-7) 16(0,-7.5) 17(0,-8) 18(0,-8.5) 19(0,-9) 20(0,-9.5) 21(0,-10) 22(0,-10.5) 23(0,-11) 24(0,-11.5) 25(0,-12) 26(0,-12.5) 27(0,-13) 28(0,-13.5) 29(0,-14) 30(0,-14.5) 31(0,-15) 32(0,-15.5) 33(0,-16) 34(0,-16.5) 35(0,-17) 36(0,-17.5) 37(0,-18) 38(0,-18.5) 65(15.762,-18.5) 66(15.762,-18) 67(15.762,-17.5) 68(15.762,-17) 69(15.762,-16.5) 70(15.762,-16) 71(15.762,-15.5) 72(15.762,-15) 73(15.762,-14.5) 74(15.762,-14) 75(15.762,-13.5) 76(15.762,-13) 77(15.762,-12.5) 78(15.762,-12) 79(15.762,-11.5) 80(15.762,-11) 81(15.762,-10.5) 82(15.762,-10) 83(15.762,-9.5) 84(15.762,-9) 85(15.762,-8.5) 86(15.762,-8) 87(15.762,-7.5) 88(15.762,-7) 89(15.762,-6.5) 90(15.762,-6) 91(15.762,-5.5) 92(15.762,-5) 93(15.762,-4.5) 94(15.762,-4) 95(15.762,-3.5) 96(15.762,-3) 97(15.762,-2.5) 98(15.762,-2) 99(15.762,-1.5) 100(15.762,-1) 101(15.762,-0.5) 102(15.762,0)
  rect 0.3x2.286 smd: 39(1.631,-19.906) 40(2.131,-19.906) 41(2.631,-19.906) 42(3.131,-19.906) 43(3.631,-19.906) 44(4.131,-19.906) 45(4.631,-19.906) 46(5.131,-19.906) 47(5.631,-19.906) 48(6.131,-19.906) 49(6.631,-19.906) 50(7.131,-19.906) 51(7.631,-19.906) 52(8.131,-19.906) 53(8.631,-19.906) 54(9.131,-19.906) 55(9.631,-19.906) 56(10.131,-19.906) 57(10.631,-19.906) 58(11.131,-19.906) 59(11.631,-19.906) 60(12.131,-19.906) 61(12.631,-19.906) 62(13.131,-19.906) 63(13.631,-19.906) 64(14.131,-19.906) 103(14.131,1.381) 104(13.631,1.381) 105(13.131,1.381) 106(12.631,1.381) 107(12.131,1.381) 108(11.631,1.381) 109(11.131,1.381) 110(10.631,1.381) 111(10.131,1.381) 112(9.631,1.381) 113(9.131,1.381) 114(8.631,1.381) 115(8.131,1.381) 116(7.631,1.381) 117(7.131,1.381) 118(6.631,1.381) 119(6.131,1.381) 120(5.631,1.381) 121(5.131,1.381) 122(4.631,1.381) 123(4.131,1.381) 124(3.631,1.381) 125(3.131,1.381) 126(2.631,1.381) 127(2.131,1.381) 128(1.631,1.381)
  silkscreen extent 1.65,-18.03 14.1,0
"USB_B right angle" [mil]
  rect 62x62 hole 42: 1(0,0)
  round 62 hole 42: 2(-98.42,0) 3(-98.42,-78.74) 4(0,-78.74)
  round 128 hole 92: E1(-286.22,-185.43) E2(187.8,-185.43)
  silkscreen extent -374,-551 276,39

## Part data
C1 C13 C29 C31 C32 C40 C41 C55 C56 C69 C70 C77 C78 C101 C102 C104 C107 C109 C111 C112 C126 C127 C136: library part ELECTRO1
C2 C5 C10 C11 C12 C14 C15 C18 C20 C21 C22 C25 C26 C27 C28 C30 C33 C34 C35 C36 C37 C38 C39 C42 C43 C44 C45 C46 C47 C48 C50 C51 C52 C53 C54 C57 C58 C59 C60 C61 C62 C64 C65 C66 C67 C81 C82 C83 C84 C85 C86 C87 C88 C89 C90 C91 C92 C93 C94 C95 C96 C97 C98 C99 C103 C108 C114 C115 C116 C117 C118 C119 C120 C121 C122 C123 C124 C125 C128 C129 C130 C131 C132 C133 C134 C135: library part CAP, "Capacitor"
C3 C4 C6 C7 C8 C9 C16 C17 C19 C23 C24 C49 C63 C68 C71 C72 C73 C74 C75 C76 C79 C80 C100 C105 C106 C110 C113 C137 C138 C140 C141 C142: library part CAP
D2 D5: library part LED, "LED"
J2: library part QMSS-EM-PC4, "SAMTEC QMSS W/PWR PINS"
J3 J5: library part HEADER5X2
J4: library part USB
J6: library part HEADER7X2
J8: "Connector"
L1 L2 L3 L4 L5 L6 L7: library part INDUCTOR1
R1 R2 R3 R4 R5 R6 R7 R8 R9 R10 R11 R12 R13 R14 R15 R16 R17 R18 R19 R20 R21 R22 R23 R24 R25 R26 R27 R28 R29 R30 R31 R32 R33 R34 R35 R36 R37 R38 R39 R40 R41 R42 R43 R44 R45 R46 R47 R56 R57 R58 R59: library part RES, "Resistor"
R48 R49 R50 R51 R52 R53 R54 R55: library part RES1
RN1 RN2 RN3 RN4 RN5: library part "R 4 NET"
TP1 TP3: "Test Point"
TP2: library part "Test point", "Test Point"
U1: "EPCS4 Series, In-system programmable 3.3V serial configuration device, 8-Pin SOIC, 4-Megabit, Industrial Grade"
U2: library part OSC,DIP8
U9: "Cyclone III Family FPGA, 152 I/O Pins, 4 PLLs, 256-Pin FBGA, Speed Grade 6, Commercial Grade"
U10 U17 U23 U24: library part 74ACT125
U12 U28: library part 24LC00
U13: library part CDCLVD110A
U14: library part C5310
U15 U16 U18 U19: library part IDT72V21XX
U22: library part SN74AHC02N, "Quadruple 2-Input Positive-NOR Gate"
U25: library part SN7406N, "Hex Inverter Buffer / Driver with High-Voltage Outputs"
U26 U27: library part LT1963AEQ
U29: library part MSP430F54XX
U30 U33: library part SN75ALS176AD, "Differential Bus Transceiver"
U32: library part ACSL_6210
U44: library part SN54AC14W, "Hex Schmitt-Trigger Inverter"

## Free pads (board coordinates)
  round 50 hole 25: 0(118.11,78.74) 0(118.11,236.22) 0(118.11,551.18) 0(118.11,708.66) 0(275.59,78.74) 0(275.59,236.22) 0(275.59,551.18) 0(275.59,708.66) 1(433.07,78.74) 1(433.07,236.22) 1(433.07,393.7) 1(433.07,551.18) 1(433.07,708.66) 2(590.55,78.74) 2(590.55,236.22) 2(590.55,393.7) 2(590.55,551.18) 2(590.55,708.66) 3(748.03,78.74) 3(748.03,236.22) 3(748.03,393.7) 3(748.03,551.18) 3(748.03,708.66) 4(905.51,78.74) 4(905.51,236.22) 4(905.51,551.18) 4(905.51,708.66) 5(1062.99,78.74) 5(1062.99,236.22) 5(1062.99,551.18) 5(1062.99,708.66)
  round 236.22 hole 118: 0(196.85,393.7) 1(984.25,393.7)
  rect 1170x780 smd: 3(590,390)
  rect 1170x780 smd far side: 3(590,390)
  round 40 smd: ""(1400,2500) ""(1400,4100) ""(2500,1302) ""(2500,2135) ""(3320,1316) ""(3350,2500) ""(3350,4100) ""(3800,3100) ""(4200,2555) ""(4600,4100) ""(5055,1800)

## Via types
v1: diameter 20, hole 10, Top Layer to Bottom Layer, 647 vias
v2: diameter 25, hole 15, Top Layer to Bottom Layer, 352 vias
v3: diameter 20, hole 10, Top Layer to Bottom Layer, tented top, 151 vias
v4: diameter 20, hole 10, Top Layer to Bottom Layer, tented bottom, 1 vias

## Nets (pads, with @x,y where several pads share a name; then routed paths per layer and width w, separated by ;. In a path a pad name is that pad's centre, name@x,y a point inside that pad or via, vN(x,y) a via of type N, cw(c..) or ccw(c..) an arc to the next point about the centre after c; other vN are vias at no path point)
+3.3V: C100.2 J1.PC01 J1.PC02 J2.PC01 J2.PC02 L6.1 | length 1554.6
  Top Layer w20: J1.PC01@4397.21,453.35 4397.21,832.36 J2.PC02@4400,835.16 ; J2.PC01@4400,730 4397.76,732.24 J2.PC02@4397.76,837.4 J2.PC02@4400,835.16 ; C100.2@4915,545.01 4879.99,545.01 4830,595 L6.1@4830,765 4400,765 J2.PC02@4400,835.16
  Bottom Layer w20: J1.PC02@4397.21,453.35 4397.21,736.85 J2.PC01@4397.76,737.4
